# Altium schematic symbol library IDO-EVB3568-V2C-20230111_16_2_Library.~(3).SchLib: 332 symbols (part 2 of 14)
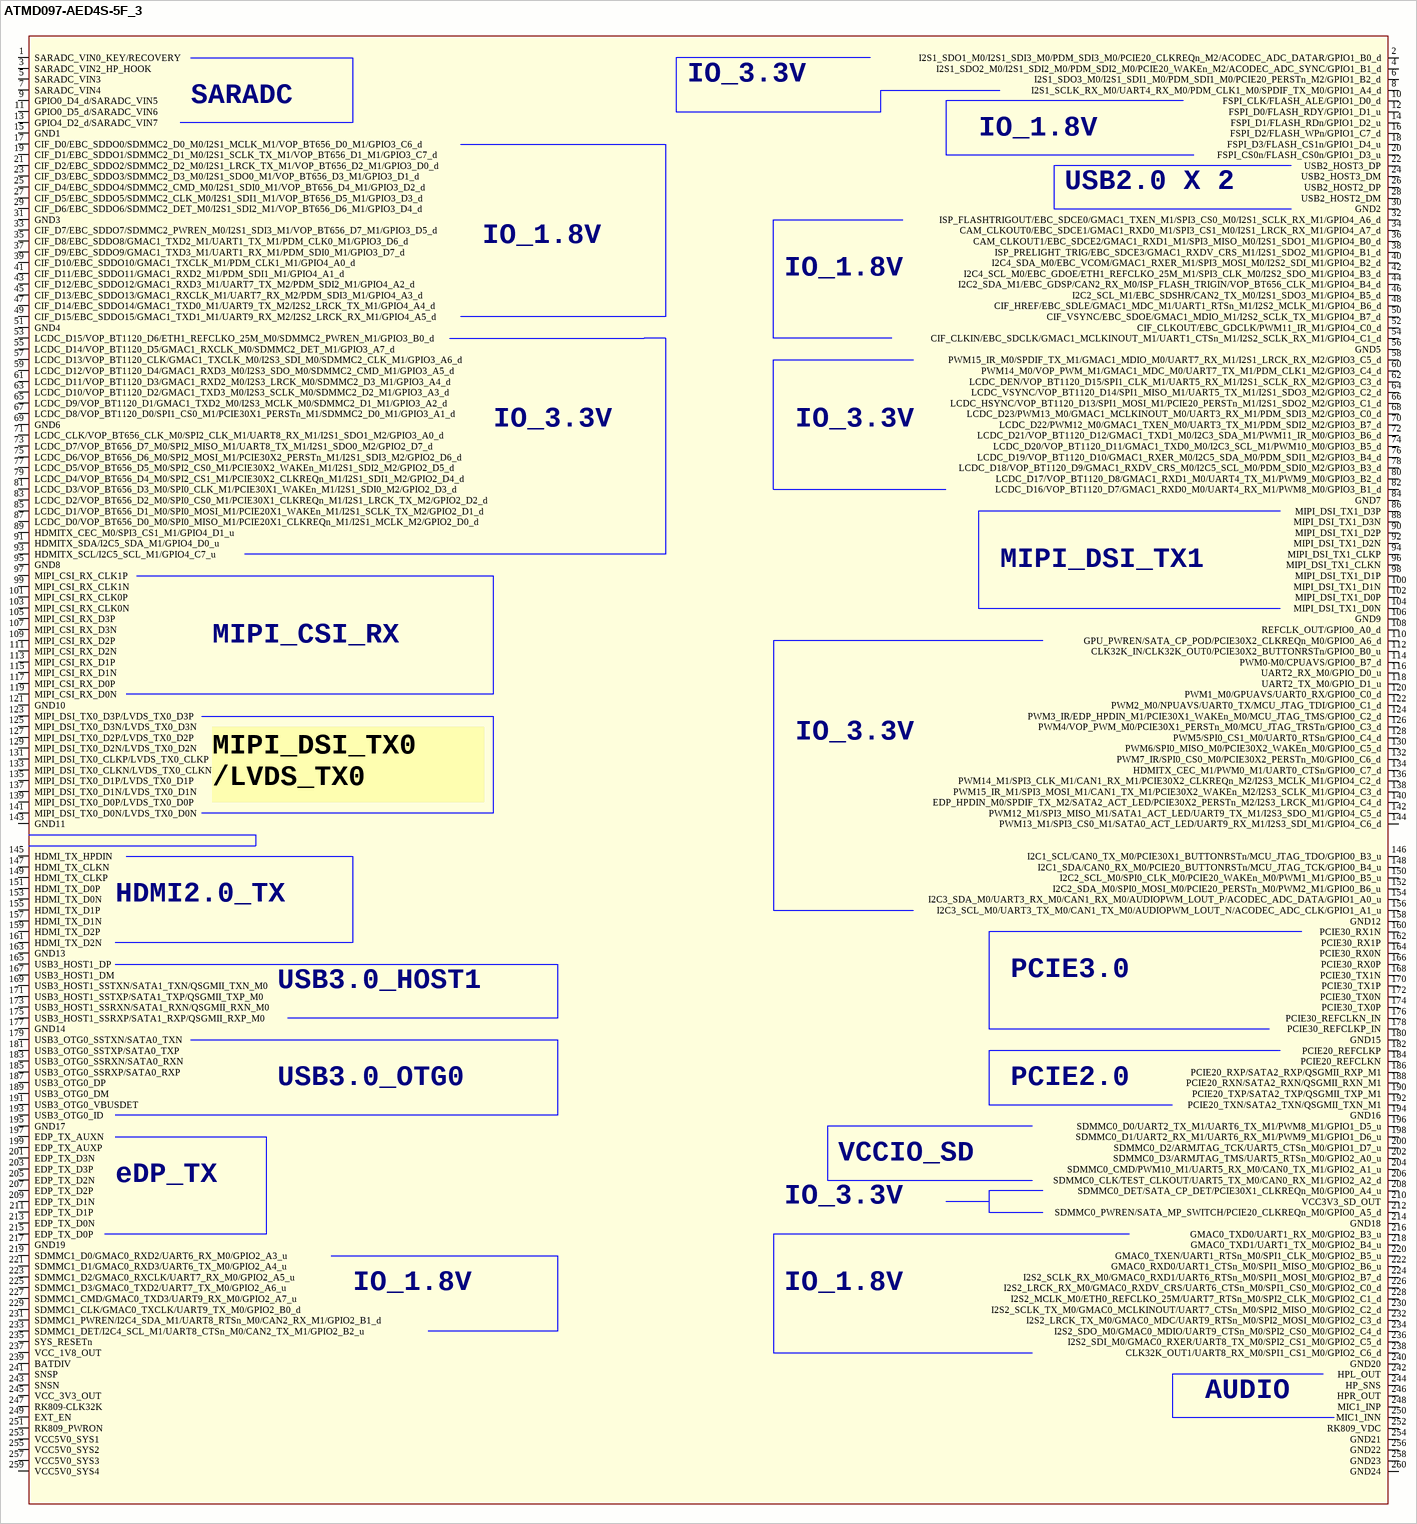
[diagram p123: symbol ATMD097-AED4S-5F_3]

## ATMD097-AED4S-5F_3
designator J?
Altium-Right: 1260; Altium-Bottom: 1360
pins: 1 SARADC_VIN0_KEY/RECOVERY, 2 I2S1_SDO1_M0/I2S1_SDI3_M0/PDM_SDI3_M0/PCIE20_CLKREQn_M2/ACODEC_ADC_DATAR/GPIO1_B0_d, 3 SARADC_VIN2_HP_HOOK, 4 I2S1_SDO2_M0/I2S1_SDI2_M0/PDM_SDI2_M0/PCIE20_WAKEn_M2/ACODEC_ADC_SYNC/GPIO1_B1_d, 5 SARADC_VIN3, 6 I2S1_SDO3_M0/I2S1_SDI1_M0/PDM_SDI1_M0/PCIE20_PERSTn_M2/GPIO1_B2_d, 7 SARADC_VIN4, 8 I2S1_SCLK_RX_M0/UART4_RX_M0/PDM_CLK1_M0/SPDIF_TX_M0/GPIO1_A4_d, 9 GPIO0_D4_d/SARADC_VIN5, 10 FSPI_CLK/FLASH_ALE/GPIO1_D0_d, 11 GPIO0_D5_d/SARADC_VIN6, 12 FSPI_D0/FLASH_RDY/GPIO1_D1_u, 13 GPIO4_D2_d/SARADC_VIN7, 14 FSPI_D1/FLASH_RDn/GPIO1_D2_u, 15 GND1, 16 FSPI_D2/FLASH_WPn/GPIO1_C7_d, 17 CIF_D0/EBC_SDDO0/SDMMC2_D0_M0/I2S1_MCLK_M1/VOP_BT656_D0_M1/GPIO3_C6_d, 18 FSPI_D3/FLASH_CS1n/GPIO1_D4_u, 19 CIF_D1/EBC_SDDO1/SDMMC2_D1_M0/I2S1_SCLK_TX_M1/VOP_BT656_D1_M1/GPIO3_C7_d, 20 FSPI_CS0n/FLASH_CS0n/GPIO1_D3_u, 21 CIF_D2/EBC_SDDO2/SDMMC2_D2_M0/I2S1_LRCK_TX_M1/VOP_BT656_D2_M1/GPIO3_D0_d, 22 USB2_HOST3_DP, 23 CIF_D3/EBC_SDDO3/SDMMC2_D3_M0/I2S1_SDO0_M1/VOP_BT656_D3_M1/GPIO3_D1_d, 24 USB2_HOST3_DM, 25 CIF_D4/EBC_SDDO4/SDMMC2_CMD_M0/I2S1_SDI0_M1/VOP_BT656_D4_M1/GPIO3_D2_d, 26 USB2_HOST2_DP, 27 CIF_D5/EBC_SDDO5/SDMMC2_CLK_M0/I2S1_SDI1_M1/VOP_BT656_D5_M1/GPIO3_D3_d, 28 USB2_HOST2_DM, 29 CIF_D6/EBC_SDDO6/SDMMC2_DET_M0/I2S1_SDI2_M1/VOP_BT656_D6_M1/GPIO3_D4_d, 30 GND2, 31 GND3, 32 ISP_FLASHTRIGOUT/EBC_SDCE0/GMAC1_TXEN_M1/SPI3_CS0_M0/I2S1_SCLK_RX_M1/GPIO4_A6_d, 33 CIF_D7/EBC_SDDO7/SDMMC2_PWREN_M0/I2S1_SDI3_M1/VOP_BT656_D7_M1/GPIO3_D5_d, 34 CAM_CLKOUT0/EBC_SDCE1/GMAC1_RXD0_M1/SPI3_CS1_M0/I2S1_LRCK_RX_M1/GPIO4_A7_d, 35 CIF_D8/EBC_SDDO8/GMAC1_TXD2_M1/UART1_TX_M1/PDM_CLK0_M1/GPIO3_D6_d, 36 CAM_CLKOUT1/EBC_SDCE2/GMAC1_RXD1_M1/SPI3_MISO_M0/I2S1_SDO1_M1/GPIO4_B0_d, 37 CIF_D9/EBC_SDDO9/GMAC1_TXD3_M1/UART1_RX_M1/PDM_SDI0_M1/GPIO3_D7_d, 38 ISP_PRELIGHT_TRIG/EBC_SDCE3/GMAC1_RXDV_CRS_M1/I2S1_SDO2_M1/GPIO4_B1_d, 39 CIF_D10/EBC_SDDO10/GMAC1_TXCLK_M1/PDM_CLK1_M1/GPIO4_A0_d, 40 I2C4_SDA_M0/EBC_VCOM/GMAC1_RXER_M1/SPI3_MOSI_M0/I2S2_SDI_M1/GPIO4_B2_d, 41 CIF_D11/EBC_SDDO11/GMAC1_RXD2_M1/PDM_SDI1_M1/GPIO4_A1_d, 42 I2C4_SCL_M0/EBC_GDOE/ETH1_REFCLKO_25M_M1/SPI3_CLK_M0/I2S2_SDO_M1/GPIO4_B3_d, 43 CIF_D12/EBC_SDDO12/GMAC1_RXD3_M1/UART7_TX_M2/PDM_SDI2_M1/GPIO4_A2_d, 44 I2C2_SDA_M1/EBC_GDSP/CAN2_RX_M0/ISP_FLASH_TRIGIN/VOP_BT656_CLK_M1/GPIO4_B4_d, 45 CIF_D13/EBC_SDDO13/GMAC1_RXCLK_M1/UART7_RX_M2/PDM_SDI3_M1/GPIO4_A3_d, 46 I2C2_SCL_M1/EBC_SDSHR/CAN2_TX_M0/I2S1_SDO3_M1/GPIO4_B5_d, 47 CIF_D14/EBC_SDDO14/GMAC1_TXD0_M1/UART9_TX_M2/I2S2_LRCK_TX_M1/GPIO4_A4_d, 48 CIF_HREF/EBC_SDLE/GMAC1_MDC_M1/UART1_RTSn_M1/I2S2_MCLK_M1/GPIO4_B6_d, 49 CIF_D15/EBC_SDDO15/GMAC1_TXD1_M1/UART9_RX_M2/I2S2_LRCK_RX_M1/GPIO4_A5_d, 50 CIF_VSYNC/EBC_SDOE/GMAC1_MDIO_M1/I2S2_SCLK_TX_M1/GPIO4_B7_d, 51 GND4, 52 CIF_CLKOUT/EBC_GDCLK/PWM11_IR_M1/GPIO4_C0_d, 53 LCDC_D15/VOP_BT1120_D6/ETH1_REFCLKO_25M_M0/SDMMC2_PWREN_M1/GPIO3_B0_d, 54 CIF_CLKIN/EBC_SDCLK/GMAC1_MCLKINOUT_M1/UART1_CTSn_M1/I2S2_SCLK_RX_M1/GPIO4_C1_d, 55 LCDC_D14/VOP_BT1120_D5/GMAC1_RXCLK_M0/SDMMC2_DET_M1/GPIO3_A7_d, 56 GND5, 57 LCDC_D13/VOP_BT1120_CLK/GMAC1_TXCLK_M0/I2S3_SDI_M0/SDMMC2_CLK_M1/GPIO3_A6_d, 58 PWM15_IR_M0/SPDIF_TX_M1/GMAC1_MDIO_M0/UART7_RX_M1/I2S1_LRCK_RX_M2/GPIO3_C5_d, 59 LCDC_D12/VOP_BT1120_D4/GMAC1_RXD3_M0/I2S3_SDO_M0/SDMMC2_CMD_M1/GPIO3_A5_d, 60 PWM14_M0/VOP_PWM_M1/GMAC1_MDC_M0/UART7_TX_M1/PDM_CLK1_M2/GPIO3_C4_d, 61 LCDC_D11/VOP_BT1120_D3/GMAC1_RXD2_M0/I2S3_LRCK_M0/SDMMC2_D3_M1/GPIO3_A4_d, 62 LCDC_DEN/VOP_BT1120_D15/SPI1_CLK_M1/UART5_RX_M1/I2S1_SCLK_RX_M2/GPIO3_C3_d, 63 LCDC_D10/VOP_BT1120_D2/GMAC1_TXD3_M0/I2S3_SCLK_M0/SDMMC2_D2_M1/GPIO3_A3_d, 64 LCDC_VSYNC/VOP_BT1120_D14/SPI1_MISO_M1/UART5_TX_M1/I2S1_SDO3_M2/GPIO3_C2_d, 65 LCDC_D9/VOP_BT1120_D1/GMAC1_TXD2_M0/I2S3_MCLK_M0/SDMMC2_D1_M1/GPIO3_A2_d, 66 LCDC_HSYNC/VOP_BT1120_D13/SPI1_MOSI_M1/PCIE20_PERSTn_M1/I2S1_SDO2_M2/GPIO3_C1_d, 67 LCDC_D8/VOP_BT1120_D0/SPI1_CS0_M1/PCIE30X1_PERSTn_M1/SDMMC2_D0_M1/GPIO3_A1_d, 68 LCDC_D23/PWM13_M0/GMAC1_MCLKINOUT_M0/UART3_RX_M1/PDM_SDI3_M2/GPIO3_C0_d, 69 GND6, 70 LCDC_D22/PWM12_M0/GMAC1_TXEN_M0/UART3_TX_M1/PDM_SDI2_M2/GPIO3_B7_d, 71 LCDC_CLK/VOP_BT656_CLK_M0/SPI2_CLK_M1/UART8_RX_M1/I2S1_SDO1_M2/GPIO3_A0_d, 72 LCDC_D21/VOP_BT1120_D12/GMAC1_TXD1_M0/I2C3_SDA_M1/PWM11_IR_M0/GPIO3_B6_d, 73 LCDC_D7/VOP_BT656_D7_M0/SPI2_MISO_M1/UART8_TX_M1/I2S1_SDO0_M2/GPIO2_D7_d, 74 LCDC_D20/VOP_BT1120_D11/GMAC1_TXD0_M0/I2C3_SCL_M1/PWM10_M0/GPIO3_B5_d, 75 LCDC_D6/VOP_BT656_D6_M0/SPI2_MOSI_M1/PCIE30X2_PERSTn_M1/I2S1_SDI3_M2/GPIO2_D6_d, 76 LCDC_D19/VOP_BT1120_D10/GMAC1_RXER_M0/I2C5_SDA_M0/PDM_SDI1_M2/GPIO3_B4_d, 77 LCDC_D5/VOP_BT656_D5_M0/SPI2_CS0_M1/PCIE30X2_WAKEn_M1/I2S1_SDI2_M2/GPIO2_D5_d, 78 LCDC_D18/VOP_BT1120_D9/GMAC1_RXDV_CRS_M0/I2C5_SCL_M0/PDM_SDI0_M2/GPIO3_B3_d, 79 LCDC_D4/VOP_BT656_D4_M0/SPI2_CS1_M1/PCIE30X2_CLKREQn_M1/I2S1_SDI1_M2/GPIO2_D4_d, 80 LCDC_D17/VOP_BT1120_D8/GMAC1_RXD1_M0/UART4_TX_M1/PWM9_M0/GPIO3_B2_d, 81 LCDC_D3/VOP_BT656_D3_M0/SPI0_CLK_M1/PCIE30X1_WAKEn_M1/I2S1_SDI0_M2/GPIO2_D3_d, 82 LCDC_D16/VOP_BT1120_D7/GMAC1_RXD0_M0/UART4_RX_M1/PWM8_M0/GPIO3_B1_d, 83 LCDC_D2/VOP_BT656_D2_M0/SPI0_CS0_M1/PCIE30X1_CLKREQn_M1/I2S1_LRCK_TX_M2/GPIO2_D2_d, 84 GND7, 85 LCDC_D1/VOP_BT656_D1_M0/SPI0_MOSI_M1/PCIE20X1_WAKEn_M1/I2S1_SCLK_TX_M2/GPIO2_D1_d, 86 MIPI_DSI_TX1_D3P, 87 LCDC_D0/VOP_BT656_D0_M0/SPI0_MISO_M1/PCIE20X1_CLKREQn_M1/I2S1_MCLK_M2/GPIO2_D0_d, 88 MIPI_DSI_TX1_D3N, 89 HDMITX_CEC_M0/SPI3_CS1_M1/GPIO4_D1_u, 90 MIPI_DSI_TX1_D2P, 91 HDMITX_SDA/I2C5_SDA_M1/GPIO4_D0_u, 92 MIPI_DSI_TX1_D2N, 93 HDMITX_SCL/I2C5_SCL_M1/GPIO4_C7_u, 94 MIPI_DSI_TX1_CLKP, 95 GND8, 96 MIPI_DSI_TX1_CLKN, 97 MIPI_CSI_RX_CLK1P, 98 MIPI_DSI_TX1_D1P, 99 MIPI_CSI_RX_CLK1N, 100 MIPI_DSI_TX1_D1N, 101 MIPI_CSI_RX_CLK0P, 102 MIPI_DSI_TX1_D0P, 103 MIPI_CSI_RX_CLK0N, 104 MIPI_DSI_TX1_D0N, 105 MIPI_CSI_RX_D3P, 106 GND9, 107 MIPI_CSI_RX_D3N, 108 REFCLK_OUT/GPIO0_A0_d, 109 MIPI_CSI_RX_D2P, 110 GPU_PWREN/SATA_CP_POD/PCIE30X2_CLKREQn_M0/GPIO0_A6_d, 111 MIPI_CSI_RX_D2N, 112 CLK32K_IN/CLK32K_OUT0/PCIE30X2_BUTTONRSTn/GPIO0_B0_u, 113 MIPI_CSI_RX_D1P, 114 PWM0-M0/CPUAVS/GPIO0_B7_d, 115 MIPI_CSI_RX_D1N, 116 UART2_RX_M0/GPIO_D0_u, 117 MIPI_CSI_RX_D0P, 118 UART2_TX_M0/GPIO_D1_u, 119 MIPI_CSI_RX_D0N, 120 PWM1_M0/GPUAVS/UART0_RX/GPIO0_C0_d, 121 GND10, 122 PWM2_M0/NPUAVS/UART0_TX/MCU_JTAG_TDI/GPIO0_C1_d, 123 MIPI_DSI_TX0_D3P/LVDS_TX0_D3P, 124 PWM3_IR/EDP_HPDIN_M1/PCIE30X1_WAKEn_M0/MCU_JTAG_TMS/GPIO0_C2_d, 125 MIPI_DSI_TX0_D3N/LVDS_TX0_D3N, 126 PWM4/VOP_PWM_M0/PCIE30X1_PERSTn_M0/MCU_JTAG_TRSTn/GPIO0_C3_d, 127 MIPI_DSI_TX0_D2P/LVDS_TX0_D2P, 128 PWM5/SPI0_CS1_M0/UART0_RTSn/GPIO0_C4_d, 129 MIPI_DSI_TX0_D2N/LVDS_TX0_D2N, 130 PWM6/SPI0_MISO_M0/PCIE30X2_WAKEn_M0/GPIO0_C5_d, 131 MIPI_DSI_TX0_CLKP/LVDS_TX0_CLKP, 132 PWM7_IR/SPI0_CS0_M0/PCIE30X2_PERSTn_M0/GPIO0_C6_d, 133 MIPI_DSI_TX0_CLKN/LVDS_TX0_CLKN, 134 HDMITX_CEC_M1/PWM0_M1/UART0_CTSn/GPIO0_C7_d, 135 MIPI_DSI_TX0_D1P/LVDS_TX0_D1P, 136 PWM14_M1/SPI3_CLK_M1/CAN1_RX_M1/PCIE30X2_CLKREQn_M2/I2S3_MCLK_M1/GPIO4_C2_d, 137 MIPI_DSI_TX0_D1N/LVDS_TX0_D1N, 138 PWM15_IR_M1/SPI3_MOSI_M1/CAN1_TX_M1/PCIE30X2_WAKEn_M2/I2S3_SCLK_M1/GPIO4_C3_d, 139 MIPI_DSI_TX0_D0P/LVDS_TX0_D0P, 140 EDP_HPDIN_M0/SPDIF_TX_M2/SATA2_ACT_LED/PCIE30X2_PERSTn_M2/I2S3_LRCK_M1/GPIO4_C4_d, 141 MIPI_DSI_TX0_D0N/LVDS_TX0_D0N, 142 PWM12_M1/SPI3_MISO_M1/SATA1_ACT_LED/UART9_TX_M1/I2S3_SDO_M1/GPIO4_C5_d, 143 GND11, 144 PWM13_M1/SPI3_CS0_M1/SATA0_ACT_LED/UART9_RX_M1/I2S3_SDI_M1/GPIO4_C6_d, 145 HDMI_TX_HPDIN, 146 I2C1_SCL/CAN0_TX_M0/PCIE30X1_BUTTONRSTn/MCU_JTAG_TDO/GPIO0_B3_u, 147 HDMI_TX_CLKN, 148 I2C1_SDA/CAN0_RX_M0/PCIE20_BUTTONRSTn/MCU_JTAG_TCK/GPIO0_B4_u, 149 HDMI_TX_CLKP, 150 I2C2_SCL_M0/SPI0_CLK_M0/PCIE20_WAKEn_M0/PWM1_M1/GPIO0_B5_u, 151 HDMI_TX_D0P, 152 I2C2_SDA_M0/SPI0_MOSI_M0/PCIE20_PERSTn_M0/PWM2_M1/GPIO0_B6_u, 153 HDMI_TX_D0N, 154 I2C3_SDA_M0/UART3_RX_M0/CAN1_RX_M0/AUDIOPWM_LOUT_P/ACODEC_ADC_DATA/GPIO1_A0_u, 155 HDMI_TX_D1P, 156 I2C3_SCL_M0/UART3_TX_M0/CAN1_TX_M0/AUDIOPWM_LOUT_N/ACODEC_ADC_CLK/GPIO1_A1_u, 157 HDMI_TX_D1N, 158 GND12, 159 HDMI_TX_D2P, 160 PCIE30_RX1N, 161 HDMI_TX_D2N, 162 PCIE30_RX1P, 163 GND13, 164 PCIE30_RX0N, 165 USB3_HOST1_DP, 166 PCIE30_RX0P, 167 USB3_HOST1_DM, 168 PCIE30_TX1N, 169 USB3_HOST1_SSTXN/SATA1_TXN/QSGMII_TXN_M0, 170 PCIE30_TX1P, 171 USB3_HOST1_SSTXP/SATA1_TXP/QSGMII_TXP_M0, 172 PCIE30_TX0N, 173 USB3_HOST1_SSRXN/SATA1_RXN/QSGMII_RXN_M0, 174 PCIE30_TX0P, 175 USB3_HOST1_SSRXP/SATA1_RXP/QSGMII_RXP_M0, 176 PCIE30_REFCLKN_IN, 177 GND14, 178 PCIE30_REFCLKP_IN, 179 USB3_OTG0_SSTXN/SATA0_TXN, 180 GND15, 181 USB3_OTG0_SSTXP/SATA0_TXP, 182 PCIE20_REFCLKP, 183 USB3_OTG0_SSRXN/SATA0_RXN, 184 PCIE20_REFCLKN, 185 USB3_OTG0_SSRXP/SATA0_RXP, 186 PCIE20_RXP/SATA2_RXP/QSGMII_RXP_M1, 187 USB3_OTG0_DP, 188 PCIE20_RXN/SATA2_RXN/QSGMII_RXN_M1, 189 USB3_OTG0_DM, 190 PCIE20_TXP/SATA2_TXP/QSGMII_TXP_M1, 191 USB3_OTG0_VBUSDET, 192 PCIE20_TXN/SATA2_TXN/QSGMII_TXN_M1, 193 USB3_OTG0_ID, 194 GND16, 195 GND17, 196 SDMMC0_D0/UART2_TX_M1/UART6_TX_M1/PWM8_M1/GPIO1_D5_u, 197 EDP_TX_AUXN, 198 SDMMC0_D1/UART2_RX_M1/UART6_RX_M1/PWM9_M1/GPIO1_D6_u, 199 EDP_TX_AUXP, 200 SDMMC0_D2/ARMJTAG_TCK/UART5_CTSn_M0/GPIO1_D7_u, 201 EDP_TX_D3N, 202 SDMMC0_D3/ARMJTAG_TMS/UART5_RTSn_M0/GPIO2_A0_u, 203 EDP_TX_D3P, 204 SDMMC0_CMD/PWM10_M1/UART5_RX_M0/CAN0_TX_M1/GPIO2_A1_u, 205 EDP_TX_D2N, 206 SDMMC0_CLK/TEST_CLKOUT/UART5_TX_M0/CAN0_RX_M1/GPIO2_A2_d, 207 EDP_TX_D2P, 208 SDMMC0_DET/SATA_CP_DET/PCIE30X1_CLKREQn_M0/GPIO0_A4_u, 209 EDP_TX_D1N, 210 VCC3V3_SD_OUT, 211 EDP_TX_D1P, 212 SDMMC0_PWREN/SATA_MP_SWITCH/PCIE20_CLKREQn_M0/GPIO0_A5_d, 213 EDP_TX_D0N, 214 GND18, 215 EDP_TX_D0P, 216 GMAC0_TXD0/UART1_RX_M0/GPIO2_B3_u, 217 GND19, 218 GMAC0_TXD1/UART1_TX_M0/GPIO2_B4_u, 219 SDMMC1_D0/GMAC0_RXD2/UART6_RX_M0/GPIO2_A3_u, 220 GMAC0_TXEN/UART1_RTSn_M0/SPI1_CLK_M0/GPIO2_B5_u, 221 SDMMC1_D1/GMAC0_RXD3/UART6_TX_M0/GPIO2_A4_u, 222 GMAC0_RXD0/UART1_CTSn_M0/SPI1_MISO_M0/GPIO2_B6_u, 223 SDMMC1_D2/GMAC0_RXCLK/UART7_RX_M0/GPIO2_A5_u, 224 I2S2_SCLK_RX_M0/GMAC0_RXD1/UART6_RTSn_M0/SPI1_MOSI_M0/GPIO2_B7_d, 225 SDMMC1_D3/GMAC0_TXD2/UART7_TX_M0/GPIO2_A6_u, 226 I2S2_LRCK_RX_M0/GMAC0_RXDV_CRS/UART6_CTSn_M0/SPI1_CS0_M0/GPIO2_C0_d, 227 SDMMC1_CMD/GMAC0_TXD3/UART9_RX_M0/GPIO2_A7_u, 228 I2S2_MCLK_M0/ETH0_REFCLKO_25M/UART7_RTSn_M0/SPI2_CLK_M0/GPIO2_C1_d, 229 SDMMC1_CLK/GMAC0_TXCLK/UART9_TX_M0/GPIO2_B0_d, 230 I2S2_SCLK_TX_M0/GMAC0_MCLKINOUT/UART7_CTSn_M0/SPI2_MISO_M0/GPIO2_C2_d, 231 SDMMC1_PWREN/I2C4_SDA_M1/UART8_RTSn_M0/CAN2_RX_M1/GPIO2_B1_d, 232 I2S2_LRCK_TX_M0/GMAC0_MDC/UART9_RTSn_M0/SPI2_MOSI_M0/GPIO2_C3_d, 233 SDMMC1_DET/I2C4_SCL_M1/UART8_CTSn_M0/CAN2_TX_M1/GPIO2_B2_u, 234 I2S2_SDO_M0/GMAC0_MDIO/UART9_CTSn_M0/SPI2_CS0_M0/GPIO2_C4_d, 235 SYS_RESETn, 236 I2S2_SDI_M0/GMAC0_RXER/UART8_TX_M0/SPI2_CS1_M0/GPIO2_C5_d, 237 VCC_1V8_OUT, 238 CLK32K_OUT1/UART8_RX_M0/SPI1_CS1_M0/GPIO2_C6_d, 239 BATDIV, 240 GND20, 241 SNSP, 242 HPL_OUT, 243 SNSN, 244 HP_SNS, 245 VCC_3V3_OUT, 246 HPR_OUT, 247 RK809-CLK32K, 248 MIC1_INP, 249 EXT_EN, 250 MIC1_INN, 251 RK809_PWRON, 252 RK809_VDC, 253 VCC5V0_SYS1, 254 GND21, 255 VCC5V0_SYS2, 256 GND22, 257 VCC5V0_SYS3, 258 GND23, 259 VCC5V0_SYS4, 260 GND24

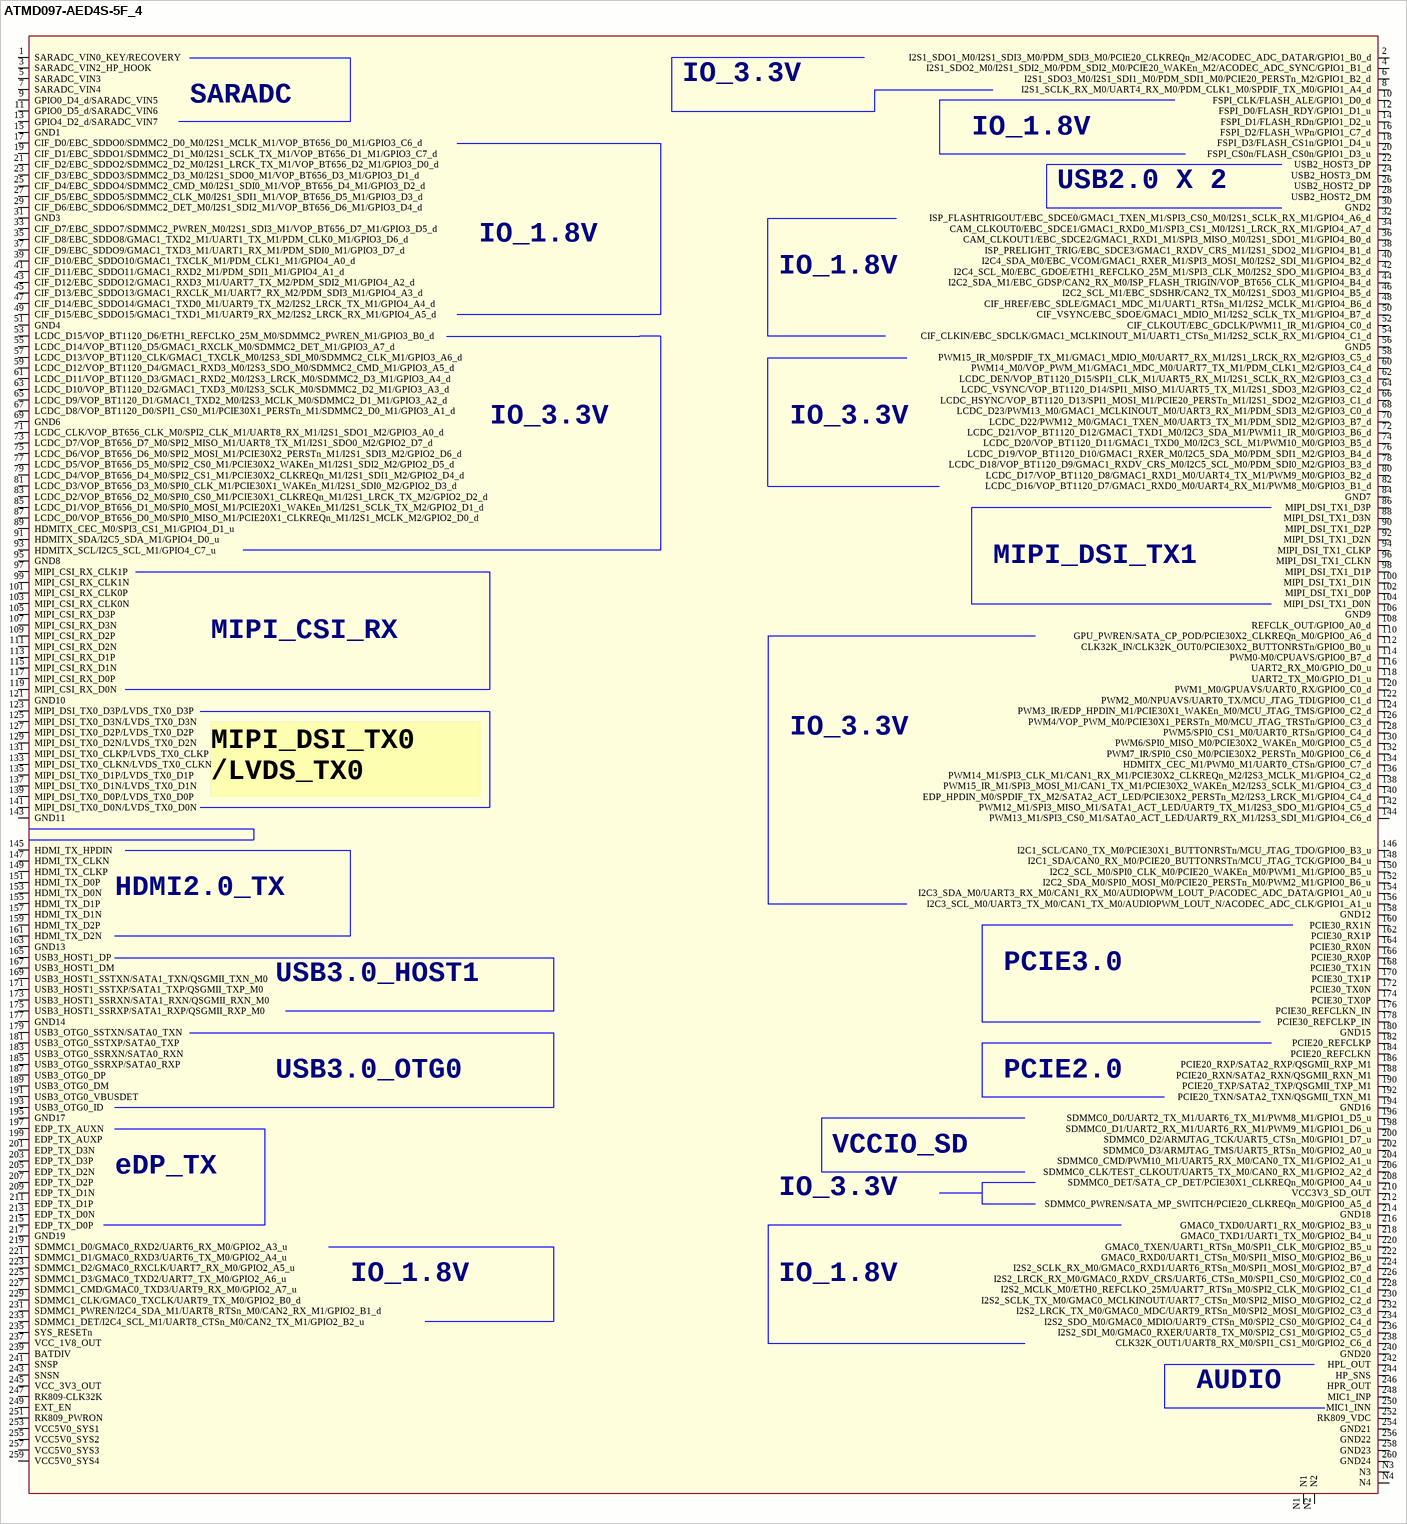
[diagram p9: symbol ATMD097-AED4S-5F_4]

## ATMD097-AED4S-5F_4
designator J?
Altium-Right: 1260; Altium-Bottom: 1360
pins: 1 SARADC_VIN0_KEY/RECOVERY, 2 I2S1_SDO1_M0/I2S1_SDI3_M0/PDM_SDI3_M0/PCIE20_CLKREQn_M2/ACODEC_ADC_DATAR/GPIO1_B0_d, 3 SARADC_VIN2_HP_HOOK, 4 I2S1_SDO2_M0/I2S1_SDI2_M0/PDM_SDI2_M0/PCIE20_WAKEn_M2/ACODEC_ADC_SYNC/GPIO1_B1_d, 5 SARADC_VIN3, 6 I2S1_SDO3_M0/I2S1_SDI1_M0/PDM_SDI1_M0/PCIE20_PERSTn_M2/GPIO1_B2_d, 7 SARADC_VIN4, 8 I2S1_SCLK_RX_M0/UART4_RX_M0/PDM_CLK1_M0/SPDIF_TX_M0/GPIO1_A4_d, 9 GPIO0_D4_d/SARADC_VIN5, 10 FSPI_CLK/FLASH_ALE/GPIO1_D0_d, 11 GPIO0_D5_d/SARADC_VIN6, 12 FSPI_D0/FLASH_RDY/GPIO1_D1_u, 13 GPIO4_D2_d/SARADC_VIN7, 14 FSPI_D1/FLASH_RDn/GPIO1_D2_u, 15 GND1, 16 FSPI_D2/FLASH_WPn/GPIO1_C7_d, 17 CIF_D0/EBC_SDDO0/SDMMC2_D0_M0/I2S1_MCLK_M1/VOP_BT656_D0_M1/GPIO3_C6_d, 18 FSPI_D3/FLASH_CS1n/GPIO1_D4_u, 19 CIF_D1/EBC_SDDO1/SDMMC2_D1_M0/I2S1_SCLK_TX_M1/VOP_BT656_D1_M1/GPIO3_C7_d, 20 FSPI_CS0n/FLASH_CS0n/GPIO1_D3_u, 21 CIF_D2/EBC_SDDO2/SDMMC2_D2_M0/I2S1_LRCK_TX_M1/VOP_BT656_D2_M1/GPIO3_D0_d, 22 USB2_HOST3_DP, 23 CIF_D3/EBC_SDDO3/SDMMC2_D3_M0/I2S1_SDO0_M1/VOP_BT656_D3_M1/GPIO3_D1_d, 24 USB2_HOST3_DM, 25 CIF_D4/EBC_SDDO4/SDMMC2_CMD_M0/I2S1_SDI0_M1/VOP_BT656_D4_M1/GPIO3_D2_d, 26 USB2_HOST2_DP, 27 CIF_D5/EBC_SDDO5/SDMMC2_CLK_M0/I2S1_SDI1_M1/VOP_BT656_D5_M1/GPIO3_D3_d, 28 USB2_HOST2_DM, 29 CIF_D6/EBC_SDDO6/SDMMC2_DET_M0/I2S1_SDI2_M1/VOP_BT656_D6_M1/GPIO3_D4_d, 30 GND2, 31 GND3, 32 ISP_FLASHTRIGOUT/EBC_SDCE0/GMAC1_TXEN_M1/SPI3_CS0_M0/I2S1_SCLK_RX_M1/GPIO4_A6_d, 33 CIF_D7/EBC_SDDO7/SDMMC2_PWREN_M0/I2S1_SDI3_M1/VOP_BT656_D7_M1/GPIO3_D5_d, 34 CAM_CLKOUT0/EBC_SDCE1/GMAC1_RXD0_M1/SPI3_CS1_M0/I2S1_LRCK_RX_M1/GPIO4_A7_d, 35 CIF_D8/EBC_SDDO8/GMAC1_TXD2_M1/UART1_TX_M1/PDM_CLK0_M1/GPIO3_D6_d, 36 CAM_CLKOUT1/EBC_SDCE2/GMAC1_RXD1_M1/SPI3_MISO_M0/I2S1_SDO1_M1/GPIO4_B0_d, 37 CIF_D9/EBC_SDDO9/GMAC1_TXD3_M1/UART1_RX_M1/PDM_SDI0_M1/GPIO3_D7_d, 38 ISP_PRELIGHT_TRIG/EBC_SDCE3/GMAC1_RXDV_CRS_M1/I2S1_SDO2_M1/GPIO4_B1_d, 39 CIF_D10/EBC_SDDO10/GMAC1_TXCLK_M1/PDM_CLK1_M1/GPIO4_A0_d, 40 I2C4_SDA_M0/EBC_VCOM/GMAC1_RXER_M1/SPI3_MOSI_M0/I2S2_SDI_M1/GPIO4_B2_d, 41 CIF_D11/EBC_SDDO11/GMAC1_RXD2_M1/PDM_SDI1_M1/GPIO4_A1_d, 42 I2C4_SCL_M0/EBC_GDOE/ETH1_REFCLKO_25M_M1/SPI3_CLK_M0/I2S2_SDO_M1/GPIO4_B3_d, 43 CIF_D12/EBC_SDDO12/GMAC1_RXD3_M1/UART7_TX_M2/PDM_SDI2_M1/GPIO4_A2_d, 44 I2C2_SDA_M1/EBC_GDSP/CAN2_RX_M0/ISP_FLASH_TRIGIN/VOP_BT656_CLK_M1/GPIO4_B4_d, 45 CIF_D13/EBC_SDDO13/GMAC1_RXCLK_M1/UART7_RX_M2/PDM_SDI3_M1/GPIO4_A3_d, 46 I2C2_SCL_M1/EBC_SDSHR/CAN2_TX_M0/I2S1_SDO3_M1/GPIO4_B5_d, 47 CIF_D14/EBC_SDDO14/GMAC1_TXD0_M1/UART9_TX_M2/I2S2_LRCK_TX_M1/GPIO4_A4_d, 48 CIF_HREF/EBC_SDLE/GMAC1_MDC_M1/UART1_RTSn_M1/I2S2_MCLK_M1/GPIO4_B6_d, 49 CIF_D15/EBC_SDDO15/GMAC1_TXD1_M1/UART9_RX_M2/I2S2_LRCK_RX_M1/GPIO4_A5_d, 50 CIF_VSYNC/EBC_SDOE/GMAC1_MDIO_M1/I2S2_SCLK_TX_M1/GPIO4_B7_d, 51 GND4, 52 CIF_CLKOUT/EBC_GDCLK/PWM11_IR_M1/GPIO4_C0_d, 53 LCDC_D15/VOP_BT1120_D6/ETH1_REFCLKO_25M_M0/SDMMC2_PWREN_M1/GPIO3_B0_d, 54 CIF_CLKIN/EBC_SDCLK/GMAC1_MCLKINOUT_M1/UART1_CTSn_M1/I2S2_SCLK_RX_M1/GPIO4_C1_d, 55 LCDC_D14/VOP_BT1120_D5/GMAC1_RXCLK_M0/SDMMC2_DET_M1/GPIO3_A7_d, 56 GND5, 57 LCDC_D13/VOP_BT1120_CLK/GMAC1_TXCLK_M0/I2S3_SDI_M0/SDMMC2_CLK_M1/GPIO3_A6_d, 58 PWM15_IR_M0/SPDIF_TX_M1/GMAC1_MDIO_M0/UART7_RX_M1/I2S1_LRCK_RX_M2/GPIO3_C5_d, 59 LCDC_D12/VOP_BT1120_D4/GMAC1_RXD3_M0/I2S3_SDO_M0/SDMMC2_CMD_M1/GPIO3_A5_d, 60 PWM14_M0/VOP_PWM_M1/GMAC1_MDC_M0/UART7_TX_M1/PDM_CLK1_M2/GPIO3_C4_d, 61 LCDC_D11/VOP_BT1120_D3/GMAC1_RXD2_M0/I2S3_LRCK_M0/SDMMC2_D3_M1/GPIO3_A4_d, 62 LCDC_DEN/VOP_BT1120_D15/SPI1_CLK_M1/UART5_RX_M1/I2S1_SCLK_RX_M2/GPIO3_C3_d, 63 LCDC_D10/VOP_BT1120_D2/GMAC1_TXD3_M0/I2S3_SCLK_M0/SDMMC2_D2_M1/GPIO3_A3_d, 64 LCDC_VSYNC/VOP_BT1120_D14/SPI1_MISO_M1/UART5_TX_M1/I2S1_SDO3_M2/GPIO3_C2_d, 65 LCDC_D9/VOP_BT1120_D1/GMAC1_TXD2_M0/I2S3_MCLK_M0/SDMMC2_D1_M1/GPIO3_A2_d, 66 LCDC_HSYNC/VOP_BT1120_D13/SPI1_MOSI_M1/PCIE20_PERSTn_M1/I2S1_SDO2_M2/GPIO3_C1_d, 67 LCDC_D8/VOP_BT1120_D0/SPI1_CS0_M1/PCIE30X1_PERSTn_M1/SDMMC2_D0_M1/GPIO3_A1_d, 68 LCDC_D23/PWM13_M0/GMAC1_MCLKINOUT_M0/UART3_RX_M1/PDM_SDI3_M2/GPIO3_C0_d, 69 GND6, 70 LCDC_D22/PWM12_M0/GMAC1_TXEN_M0/UART3_TX_M1/PDM_SDI2_M2/GPIO3_B7_d, 71 LCDC_CLK/VOP_BT656_CLK_M0/SPI2_CLK_M1/UART8_RX_M1/I2S1_SDO1_M2/GPIO3_A0_d, 72 LCDC_D21/VOP_BT1120_D12/GMAC1_TXD1_M0/I2C3_SDA_M1/PWM11_IR_M0/GPIO3_B6_d, 73 LCDC_D7/VOP_BT656_D7_M0/SPI2_MISO_M1/UART8_TX_M1/I2S1_SDO0_M2/GPIO2_D7_d, 74 LCDC_D20/VOP_BT1120_D11/GMAC1_TXD0_M0/I2C3_SCL_M1/PWM10_M0/GPIO3_B5_d, 75 LCDC_D6/VOP_BT656_D6_M0/SPI2_MOSI_M1/PCIE30X2_PERSTn_M1/I2S1_SDI3_M2/GPIO2_D6_d, 76 LCDC_D19/VOP_BT1120_D10/GMAC1_RXER_M0/I2C5_SDA_M0/PDM_SDI1_M2/GPIO3_B4_d, 77 LCDC_D5/VOP_BT656_D5_M0/SPI2_CS0_M1/PCIE30X2_WAKEn_M1/I2S1_SDI2_M2/GPIO2_D5_d, 78 LCDC_D18/VOP_BT1120_D9/GMAC1_RXDV_CRS_M0/I2C5_SCL_M0/PDM_SDI0_M2/GPIO3_B3_d, 79 LCDC_D4/VOP_BT656_D4_M0/SPI2_CS1_M1/PCIE30X2_CLKREQn_M1/I2S1_SDI1_M2/GPIO2_D4_d, 80 LCDC_D17/VOP_BT1120_D8/GMAC1_RXD1_M0/UART4_TX_M1/PWM9_M0/GPIO3_B2_d, 81 LCDC_D3/VOP_BT656_D3_M0/SPI0_CLK_M1/PCIE30X1_WAKEn_M1/I2S1_SDI0_M2/GPIO2_D3_d, 82 LCDC_D16/VOP_BT1120_D7/GMAC1_RXD0_M0/UART4_RX_M1/PWM8_M0/GPIO3_B1_d, 83 LCDC_D2/VOP_BT656_D2_M0/SPI0_CS0_M1/PCIE30X1_CLKREQn_M1/I2S1_LRCK_TX_M2/GPIO2_D2_d, 84 GND7, 85 LCDC_D1/VOP_BT656_D1_M0/SPI0_MOSI_M1/PCIE20X1_WAKEn_M1/I2S1_SCLK_TX_M2/GPIO2_D1_d, 86 MIPI_DSI_TX1_D3P, 87 LCDC_D0/VOP_BT656_D0_M0/SPI0_MISO_M1/PCIE20X1_CLKREQn_M1/I2S1_MCLK_M2/GPIO2_D0_d, 88 MIPI_DSI_TX1_D3N, 89 HDMITX_CEC_M0/SPI3_CS1_M1/GPIO4_D1_u, 90 MIPI_DSI_TX1_D2P, 91 HDMITX_SDA/I2C5_SDA_M1/GPIO4_D0_u, 92 MIPI_DSI_TX1_D2N, 93 HDMITX_SCL/I2C5_SCL_M1/GPIO4_C7_u, 94 MIPI_DSI_TX1_CLKP, 95 GND8, 96 MIPI_DSI_TX1_CLKN, 97 MIPI_CSI_RX_CLK1P, 98 MIPI_DSI_TX1_D1P, 99 MIPI_CSI_RX_CLK1N, 100 MIPI_DSI_TX1_D1N, 101 MIPI_CSI_RX_CLK0P, 102 MIPI_DSI_TX1_D0P, 103 MIPI_CSI_RX_CLK0N, 104 MIPI_DSI_TX1_D0N, 105 MIPI_CSI_RX_D3P, 106 GND9, 107 MIPI_CSI_RX_D3N, 108 REFCLK_OUT/GPIO0_A0_d, 109 MIPI_CSI_RX_D2P, 110 GPU_PWREN/SATA_CP_POD/PCIE30X2_CLKREQn_M0/GPIO0_A6_d, 111 MIPI_CSI_RX_D2N, 112 CLK32K_IN/CLK32K_OUT0/PCIE30X2_BUTTONRSTn/GPIO0_B0_u, 113 MIPI_CSI_RX_D1P, 114 PWM0-M0/CPUAVS/GPIO0_B7_d, 115 MIPI_CSI_RX_D1N, 116 UART2_RX_M0/GPIO_D0_u, 117 MIPI_CSI_RX_D0P, 118 UART2_TX_M0/GPIO_D1_u, 119 MIPI_CSI_RX_D0N, 120 PWM1_M0/GPUAVS/UART0_RX/GPIO0_C0_d, 121 GND10, 122 PWM2_M0/NPUAVS/UART0_TX/MCU_JTAG_TDI/GPIO0_C1_d, 123 MIPI_DSI_TX0_D3P/LVDS_TX0_D3P, 124 PWM3_IR/EDP_HPDIN_M1/PCIE30X1_WAKEn_M0/MCU_JTAG_TMS/GPIO0_C2_d, 125 MIPI_DSI_TX0_D3N/LVDS_TX0_D3N, 126 PWM4/VOP_PWM_M0/PCIE30X1_PERSTn_M0/MCU_JTAG_TRSTn/GPIO0_C3_d, 127 MIPI_DSI_TX0_D2P/LVDS_TX0_D2P, 128 PWM5/SPI0_CS1_M0/UART0_RTSn/GPIO0_C4_d, 129 MIPI_DSI_TX0_D2N/LVDS_TX0_D2N, 130 PWM6/SPI0_MISO_M0/PCIE30X2_WAKEn_M0/GPIO0_C5_d, 131 MIPI_DSI_TX0_CLKP/LVDS_TX0_CLKP, 132 PWM7_IR/SPI0_CS0_M0/PCIE30X2_PERSTn_M0/GPIO0_C6_d, 133 MIPI_DSI_TX0_CLKN/LVDS_TX0_CLKN, 134 HDMITX_CEC_M1/PWM0_M1/UART0_CTSn/GPIO0_C7_d, 135 MIPI_DSI_TX0_D1P/LVDS_TX0_D1P, 136 PWM14_M1/SPI3_CLK_M1/CAN1_RX_M1/PCIE30X2_CLKREQn_M2/I2S3_MCLK_M1/GPIO4_C2_d, 137 MIPI_DSI_TX0_D1N/LVDS_TX0_D1N, 138 PWM15_IR_M1/SPI3_MOSI_M1/CAN1_TX_M1/PCIE30X2_WAKEn_M2/I2S3_SCLK_M1/GPIO4_C3_d, 139 MIPI_DSI_TX0_D0P/LVDS_TX0_D0P, 140 EDP_HPDIN_M0/SPDIF_TX_M2/SATA2_ACT_LED/PCIE30X2_PERSTn_M2/I2S3_LRCK_M1/GPIO4_C4_d, 141 MIPI_DSI_TX0_D0N/LVDS_TX0_D0N, 142 PWM12_M1/SPI3_MISO_M1/SATA1_ACT_LED/UART9_TX_M1/I2S3_SDO_M1/GPIO4_C5_d, 143 GND11, 144 PWM13_M1/SPI3_CS0_M1/SATA0_ACT_LED/UART9_RX_M1/I2S3_SDI_M1/GPIO4_C6_d, 145 HDMI_TX_HPDIN, 146 I2C1_SCL/CAN0_TX_M0/PCIE30X1_BUTTONRSTn/MCU_JTAG_TDO/GPIO0_B3_u, 147 HDMI_TX_CLKN, 148 I2C1_SDA/CAN0_RX_M0/PCIE20_BUTTONRSTn/MCU_JTAG_TCK/GPIO0_B4_u, 149 HDMI_TX_CLKP, 150 I2C2_SCL_M0/SPI0_CLK_M0/PCIE20_WAKEn_M0/PWM1_M1/GPIO0_B5_u, 151 HDMI_TX_D0P, 152 I2C2_SDA_M0/SPI0_MOSI_M0/PCIE20_PERSTn_M0/PWM2_M1/GPIO0_B6_u, 153 HDMI_TX_D0N, 154 I2C3_SDA_M0/UART3_RX_M0/CAN1_RX_M0/AUDIOPWM_LOUT_P/ACODEC_ADC_DATA/GPIO1_A0_u, 155 HDMI_TX_D1P, 156 I2C3_SCL_M0/UART3_TX_M0/CAN1_TX_M0/AUDIOPWM_LOUT_N/ACODEC_ADC_CLK/GPIO1_A1_u, 157 HDMI_TX_D1N, 158 GND12, 159 HDMI_TX_D2P, 160 PCIE30_RX1N, 161 HDMI_TX_D2N, 162 PCIE30_RX1P, 163 GND13, 164 PCIE30_RX0N, 165 USB3_HOST1_DP, 166 PCIE30_RX0P, 167 USB3_HOST1_DM, 168 PCIE30_TX1N, 169 USB3_HOST1_SSTXN/SATA1_TXN/QSGMII_TXN_M0, 170 PCIE30_TX1P, 171 USB3_HOST1_SSTXP/SATA1_TXP/QSGMII_TXP_M0, 172 PCIE30_TX0N, 173 USB3_HOST1_SSRXN/SATA1_RXN/QSGMII_RXN_M0, 174 PCIE30_TX0P, 175 USB3_HOST1_SSRXP/SATA1_RXP/QSGMII_RXP_M0, 176 PCIE30_REFCLKN_IN, 177 GND14, 178 PCIE30_REFCLKP_IN, 179 USB3_OTG0_SSTXN/SATA0_TXN, 180 GND15, 181 USB3_OTG0_SSTXP/SATA0_TXP, 182 PCIE20_REFCLKP, 183 USB3_OTG0_SSRXN/SATA0_RXN, 184 PCIE20_REFCLKN, 185 USB3_OTG0_SSRXP/SATA0_RXP, 186 PCIE20_RXP/SATA2_RXP/QSGMII_RXP_M1, 187 USB3_OTG0_DP, 188 PCIE20_RXN/SATA2_RXN/QSGMII_RXN_M1, 189 USB3_OTG0_DM, 190 PCIE20_TXP/SATA2_TXP/QSGMII_TXP_M1, 191 USB3_OTG0_VBUSDET, 192 PCIE20_TXN/SATA2_TXN/QSGMII_TXN_M1, 193 USB3_OTG0_ID, 194 GND16, 195 GND17, 196 SDMMC0_D0/UART2_TX_M1/UART6_TX_M1/PWM8_M1/GPIO1_D5_u, 197 EDP_TX_AUXN, 198 SDMMC0_D1/UART2_RX_M1/UART6_RX_M1/PWM9_M1/GPIO1_D6_u, 199 EDP_TX_AUXP, 200 SDMMC0_D2/ARMJTAG_TCK/UART5_CTSn_M0/GPIO1_D7_u, 201 EDP_TX_D3N, 202 SDMMC0_D3/ARMJTAG_TMS/UART5_RTSn_M0/GPIO2_A0_u, 203 EDP_TX_D3P, 204 SDMMC0_CMD/PWM10_M1/UART5_RX_M0/CAN0_TX_M1/GPIO2_A1_u, 205 EDP_TX_D2N, 206 SDMMC0_CLK/TEST_CLKOUT/UART5_TX_M0/CAN0_RX_M1/GPIO2_A2_d, 207 EDP_TX_D2P, 208 SDMMC0_DET/SATA_CP_DET/PCIE30X1_CLKREQn_M0/GPIO0_A4_u, 209 EDP_TX_D1N, 210 VCC3V3_SD_OUT, 211 EDP_TX_D1P, 212 SDMMC0_PWREN/SATA_MP_SWITCH/PCIE20_CLKREQn_M0/GPIO0_A5_d, 213 EDP_TX_D0N, 214 GND18, 215 EDP_TX_D0P, 216 GMAC0_TXD0/UART1_RX_M0/GPIO2_B3_u, 217 GND19, 218 GMAC0_TXD1/UART1_TX_M0/GPIO2_B4_u, 219 SDMMC1_D0/GMAC0_RXD2/UART6_RX_M0/GPIO2_A3_u, 220 GMAC0_TXEN/UART1_RTSn_M0/SPI1_CLK_M0/GPIO2_B5_u, 221 SDMMC1_D1/GMAC0_RXD3/UART6_TX_M0/GPIO2_A4_u, 222 GMAC0_RXD0/UART1_CTSn_M0/SPI1_MISO_M0/GPIO2_B6_u, 223 SDMMC1_D2/GMAC0_RXCLK/UART7_RX_M0/GPIO2_A5_u, 224 I2S2_SCLK_RX_M0/GMAC0_RXD1/UART6_RTSn_M0/SPI1_MOSI_M0/GPIO2_B7_d, 225 SDMMC1_D3/GMAC0_TXD2/UART7_TX_M0/GPIO2_A6_u, 226 I2S2_LRCK_RX_M0/GMAC0_RXDV_CRS/UART6_CTSn_M0/SPI1_CS0_M0/GPIO2_C0_d, 227 SDMMC1_CMD/GMAC0_TXD3/UART9_RX_M0/GPIO2_A7_u, 228 I2S2_MCLK_M0/ETH0_REFCLKO_25M/UART7_RTSn_M0/SPI2_CLK_M0/GPIO2_C1_d, 229 SDMMC1_CLK/GMAC0_TXCLK/UART9_TX_M0/GPIO2_B0_d, 230 I2S2_SCLK_TX_M0/GMAC0_MCLKINOUT/UART7_CTSn_M0/SPI2_MISO_M0/GPIO2_C2_d, 231 SDMMC1_PWREN/I2C4_SDA_M1/UART8_RTSn_M0/CAN2_RX_M1/GPIO2_B1_d, 232 I2S2_LRCK_TX_M0/GMAC0_MDC/UART9_RTSn_M0/SPI2_MOSI_M0/GPIO2_C3_d, 233 SDMMC1_DET/I2C4_SCL_M1/UART8_CTSn_M0/CAN2_TX_M1/GPIO2_B2_u, 234 I2S2_SDO_M0/GMAC0_MDIO/UART9_CTSn_M0/SPI2_CS0_M0/GPIO2_C4_d, 235 SYS_RESETn, 236 I2S2_SDI_M0/GMAC0_RXER/UART8_TX_M0/SPI2_CS1_M0/GPIO2_C5_d, 237 VCC_1V8_OUT, 238 CLK32K_OUT1/UART8_RX_M0/SPI1_CS1_M0/GPIO2_C6_d, 239 BATDIV, 240 GND20, 241 SNSP, 242 HPL_OUT, 243 SNSN, 244 HP_SNS, 245 VCC_3V3_OUT, 246 HPR_OUT, 247 RK809-CLK32K, 248 MIC1_INP, 249 EXT_EN, 250 MIC1_INN, 251 RK809_PWRON, 252 RK809_VDC, 253 VCC5V0_SYS1, 254 GND21, 255 VCC5V0_SYS2, 256 GND22, 257 VCC5V0_SYS3, 258 GND23, 259 VCC5V0_SYS4, 260 GND24, N1, N2, N3, N4

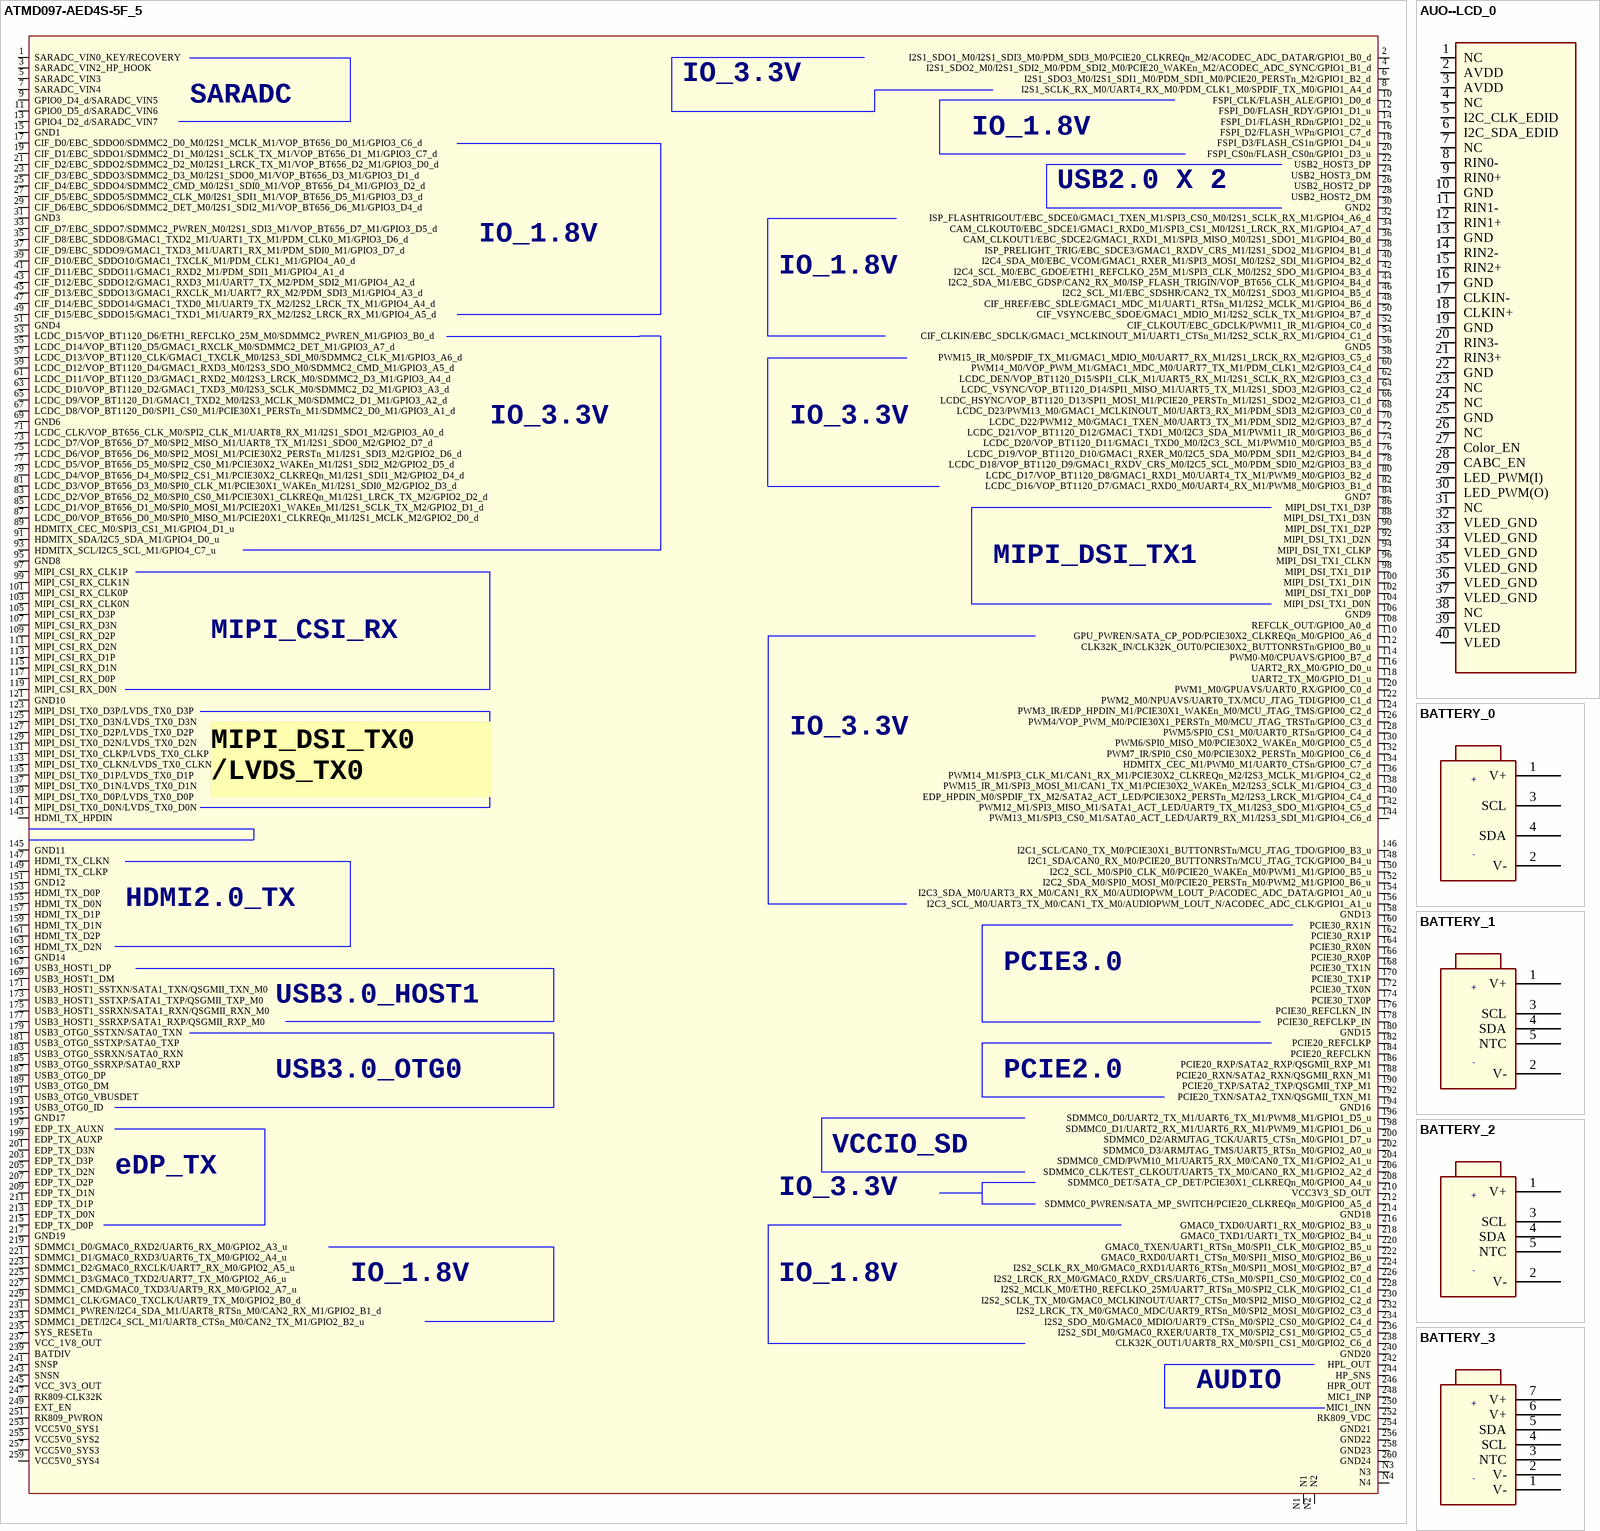
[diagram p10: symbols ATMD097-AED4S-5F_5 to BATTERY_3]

## ATMD097-AED4S-5F_5
designator J?
Altium-Right: 1260; Altium-Bottom: 1360
pins: 1 SARADC_VIN0_KEY/RECOVERY, 2 I2S1_SDO1_M0/I2S1_SDI3_M0/PDM_SDI3_M0/PCIE20_CLKREQn_M2/ACODEC_ADC_DATAR/GPIO1_B0_d, 3 SARADC_VIN2_HP_HOOK, 4 I2S1_SDO2_M0/I2S1_SDI2_M0/PDM_SDI2_M0/PCIE20_WAKEn_M2/ACODEC_ADC_SYNC/GPIO1_B1_d, 5 SARADC_VIN3, 6 I2S1_SDO3_M0/I2S1_SDI1_M0/PDM_SDI1_M0/PCIE20_PERSTn_M2/GPIO1_B2_d, 7 SARADC_VIN4, 8 I2S1_SCLK_RX_M0/UART4_RX_M0/PDM_CLK1_M0/SPDIF_TX_M0/GPIO1_A4_d, 9 GPIO0_D4_d/SARADC_VIN5, 10 FSPI_CLK/FLASH_ALE/GPIO1_D0_d, 11 GPIO0_D5_d/SARADC_VIN6, 12 FSPI_D0/FLASH_RDY/GPIO1_D1_u, 13 GPIO4_D2_d/SARADC_VIN7, 14 FSPI_D1/FLASH_RDn/GPIO1_D2_u, 15 GND1, 16 FSPI_D2/FLASH_WPn/GPIO1_C7_d, 17 CIF_D0/EBC_SDDO0/SDMMC2_D0_M0/I2S1_MCLK_M1/VOP_BT656_D0_M1/GPIO3_C6_d, 18 FSPI_D3/FLASH_CS1n/GPIO1_D4_u, 19 CIF_D1/EBC_SDDO1/SDMMC2_D1_M0/I2S1_SCLK_TX_M1/VOP_BT656_D1_M1/GPIO3_C7_d, 20 FSPI_CS0n/FLASH_CS0n/GPIO1_D3_u, 21 CIF_D2/EBC_SDDO2/SDMMC2_D2_M0/I2S1_LRCK_TX_M1/VOP_BT656_D2_M1/GPIO3_D0_d, 22 USB2_HOST3_DP, 23 CIF_D3/EBC_SDDO3/SDMMC2_D3_M0/I2S1_SDO0_M1/VOP_BT656_D3_M1/GPIO3_D1_d, 24 USB2_HOST3_DM, 25 CIF_D4/EBC_SDDO4/SDMMC2_CMD_M0/I2S1_SDI0_M1/VOP_BT656_D4_M1/GPIO3_D2_d, 26 USB2_HOST2_DP, 27 CIF_D5/EBC_SDDO5/SDMMC2_CLK_M0/I2S1_SDI1_M1/VOP_BT656_D5_M1/GPIO3_D3_d, 28 USB2_HOST2_DM, 29 CIF_D6/EBC_SDDO6/SDMMC2_DET_M0/I2S1_SDI2_M1/VOP_BT656_D6_M1/GPIO3_D4_d, 30 GND2, 31 GND3, 32 ISP_FLASHTRIGOUT/EBC_SDCE0/GMAC1_TXEN_M1/SPI3_CS0_M0/I2S1_SCLK_RX_M1/GPIO4_A6_d, 33 CIF_D7/EBC_SDDO7/SDMMC2_PWREN_M0/I2S1_SDI3_M1/VOP_BT656_D7_M1/GPIO3_D5_d, 34 CAM_CLKOUT0/EBC_SDCE1/GMAC1_RXD0_M1/SPI3_CS1_M0/I2S1_LRCK_RX_M1/GPIO4_A7_d, 35 CIF_D8/EBC_SDDO8/GMAC1_TXD2_M1/UART1_TX_M1/PDM_CLK0_M1/GPIO3_D6_d, 36 CAM_CLKOUT1/EBC_SDCE2/GMAC1_RXD1_M1/SPI3_MISO_M0/I2S1_SDO1_M1/GPIO4_B0_d, 37 CIF_D9/EBC_SDDO9/GMAC1_TXD3_M1/UART1_RX_M1/PDM_SDI0_M1/GPIO3_D7_d, 38 ISP_PRELIGHT_TRIG/EBC_SDCE3/GMAC1_RXDV_CRS_M1/I2S1_SDO2_M1/GPIO4_B1_d, 39 CIF_D10/EBC_SDDO10/GMAC1_TXCLK_M1/PDM_CLK1_M1/GPIO4_A0_d, 40 I2C4_SDA_M0/EBC_VCOM/GMAC1_RXER_M1/SPI3_MOSI_M0/I2S2_SDI_M1/GPIO4_B2_d, 41 CIF_D11/EBC_SDDO11/GMAC1_RXD2_M1/PDM_SDI1_M1/GPIO4_A1_d, 42 I2C4_SCL_M0/EBC_GDOE/ETH1_REFCLKO_25M_M1/SPI3_CLK_M0/I2S2_SDO_M1/GPIO4_B3_d, 43 CIF_D12/EBC_SDDO12/GMAC1_RXD3_M1/UART7_TX_M2/PDM_SDI2_M1/GPIO4_A2_d, 44 I2C2_SDA_M1/EBC_GDSP/CAN2_RX_M0/ISP_FLASH_TRIGIN/VOP_BT656_CLK_M1/GPIO4_B4_d, 45 CIF_D13/EBC_SDDO13/GMAC1_RXCLK_M1/UART7_RX_M2/PDM_SDI3_M1/GPIO4_A3_d, 46 I2C2_SCL_M1/EBC_SDSHR/CAN2_TX_M0/I2S1_SDO3_M1/GPIO4_B5_d, 47 CIF_D14/EBC_SDDO14/GMAC1_TXD0_M1/UART9_TX_M2/I2S2_LRCK_TX_M1/GPIO4_A4_d, 48 CIF_HREF/EBC_SDLE/GMAC1_MDC_M1/UART1_RTSn_M1/I2S2_MCLK_M1/GPIO4_B6_d, 49 CIF_D15/EBC_SDDO15/GMAC1_TXD1_M1/UART9_RX_M2/I2S2_LRCK_RX_M1/GPIO4_A5_d, 50 CIF_VSYNC/EBC_SDOE/GMAC1_MDIO_M1/I2S2_SCLK_TX_M1/GPIO4_B7_d, 51 GND4, 52 CIF_CLKOUT/EBC_GDCLK/PWM11_IR_M1/GPIO4_C0_d, 53 LCDC_D15/VOP_BT1120_D6/ETH1_REFCLKO_25M_M0/SDMMC2_PWREN_M1/GPIO3_B0_d, 54 CIF_CLKIN/EBC_SDCLK/GMAC1_MCLKINOUT_M1/UART1_CTSn_M1/I2S2_SCLK_RX_M1/GPIO4_C1_d, 55 LCDC_D14/VOP_BT1120_D5/GMAC1_RXCLK_M0/SDMMC2_DET_M1/GPIO3_A7_d, 56 GND5, 57 LCDC_D13/VOP_BT1120_CLK/GMAC1_TXCLK_M0/I2S3_SDI_M0/SDMMC2_CLK_M1/GPIO3_A6_d, 58 PWM15_IR_M0/SPDIF_TX_M1/GMAC1_MDIO_M0/UART7_RX_M1/I2S1_LRCK_RX_M2/GPIO3_C5_d, 59 LCDC_D12/VOP_BT1120_D4/GMAC1_RXD3_M0/I2S3_SDO_M0/SDMMC2_CMD_M1/GPIO3_A5_d, 60 PWM14_M0/VOP_PWM_M1/GMAC1_MDC_M0/UART7_TX_M1/PDM_CLK1_M2/GPIO3_C4_d, 61 LCDC_D11/VOP_BT1120_D3/GMAC1_RXD2_M0/I2S3_LRCK_M0/SDMMC2_D3_M1/GPIO3_A4_d, 62 LCDC_DEN/VOP_BT1120_D15/SPI1_CLK_M1/UART5_RX_M1/I2S1_SCLK_RX_M2/GPIO3_C3_d, 63 LCDC_D10/VOP_BT1120_D2/GMAC1_TXD3_M0/I2S3_SCLK_M0/SDMMC2_D2_M1/GPIO3_A3_d, 64 LCDC_VSYNC/VOP_BT1120_D14/SPI1_MISO_M1/UART5_TX_M1/I2S1_SDO3_M2/GPIO3_C2_d, 65 LCDC_D9/VOP_BT1120_D1/GMAC1_TXD2_M0/I2S3_MCLK_M0/SDMMC2_D1_M1/GPIO3_A2_d, 66 LCDC_HSYNC/VOP_BT1120_D13/SPI1_MOSI_M1/PCIE20_PERSTn_M1/I2S1_SDO2_M2/GPIO3_C1_d, 67 LCDC_D8/VOP_BT1120_D0/SPI1_CS0_M1/PCIE30X1_PERSTn_M1/SDMMC2_D0_M1/GPIO3_A1_d, 68 LCDC_D23/PWM13_M0/GMAC1_MCLKINOUT_M0/UART3_RX_M1/PDM_SDI3_M2/GPIO3_C0_d, 69 GND6, 70 LCDC_D22/PWM12_M0/GMAC1_TXEN_M0/UART3_TX_M1/PDM_SDI2_M2/GPIO3_B7_d, 71 LCDC_CLK/VOP_BT656_CLK_M0/SPI2_CLK_M1/UART8_RX_M1/I2S1_SDO1_M2/GPIO3_A0_d, 72 LCDC_D21/VOP_BT1120_D12/GMAC1_TXD1_M0/I2C3_SDA_M1/PWM11_IR_M0/GPIO3_B6_d, 73 LCDC_D7/VOP_BT656_D7_M0/SPI2_MISO_M1/UART8_TX_M1/I2S1_SDO0_M2/GPIO2_D7_d, 74 LCDC_D20/VOP_BT1120_D11/GMAC1_TXD0_M0/I2C3_SCL_M1/PWM10_M0/GPIO3_B5_d, 75 LCDC_D6/VOP_BT656_D6_M0/SPI2_MOSI_M1/PCIE30X2_PERSTn_M1/I2S1_SDI3_M2/GPIO2_D6_d, 76 LCDC_D19/VOP_BT1120_D10/GMAC1_RXER_M0/I2C5_SDA_M0/PDM_SDI1_M2/GPIO3_B4_d, 77 LCDC_D5/VOP_BT656_D5_M0/SPI2_CS0_M1/PCIE30X2_WAKEn_M1/I2S1_SDI2_M2/GPIO2_D5_d, 78 LCDC_D18/VOP_BT1120_D9/GMAC1_RXDV_CRS_M0/I2C5_SCL_M0/PDM_SDI0_M2/GPIO3_B3_d, 79 LCDC_D4/VOP_BT656_D4_M0/SPI2_CS1_M1/PCIE30X2_CLKREQn_M1/I2S1_SDI1_M2/GPIO2_D4_d, 80 LCDC_D17/VOP_BT1120_D8/GMAC1_RXD1_M0/UART4_TX_M1/PWM9_M0/GPIO3_B2_d, 81 LCDC_D3/VOP_BT656_D3_M0/SPI0_CLK_M1/PCIE30X1_WAKEn_M1/I2S1_SDI0_M2/GPIO2_D3_d, 82 LCDC_D16/VOP_BT1120_D7/GMAC1_RXD0_M0/UART4_RX_M1/PWM8_M0/GPIO3_B1_d, 83 LCDC_D2/VOP_BT656_D2_M0/SPI0_CS0_M1/PCIE30X1_CLKREQn_M1/I2S1_LRCK_TX_M2/GPIO2_D2_d, 84 GND7, 85 LCDC_D1/VOP_BT656_D1_M0/SPI0_MOSI_M1/PCIE20X1_WAKEn_M1/I2S1_SCLK_TX_M2/GPIO2_D1_d, 86 MIPI_DSI_TX1_D3P, 87 LCDC_D0/VOP_BT656_D0_M0/SPI0_MISO_M1/PCIE20X1_CLKREQn_M1/I2S1_MCLK_M2/GPIO2_D0_d, 88 MIPI_DSI_TX1_D3N, 89 HDMITX_CEC_M0/SPI3_CS1_M1/GPIO4_D1_u, 90 MIPI_DSI_TX1_D2P, 91 HDMITX_SDA/I2C5_SDA_M1/GPIO4_D0_u, 92 MIPI_DSI_TX1_D2N, 93 HDMITX_SCL/I2C5_SCL_M1/GPIO4_C7_u, 94 MIPI_DSI_TX1_CLKP, 95 GND8, 96 MIPI_DSI_TX1_CLKN, 97 MIPI_CSI_RX_CLK1P, 98 MIPI_DSI_TX1_D1P, 99 MIPI_CSI_RX_CLK1N, 100 MIPI_DSI_TX1_D1N, 101 MIPI_CSI_RX_CLK0P, 102 MIPI_DSI_TX1_D0P, 103 MIPI_CSI_RX_CLK0N, 104 MIPI_DSI_TX1_D0N, 105 MIPI_CSI_RX_D3P, 106 GND9, 107 MIPI_CSI_RX_D3N, 108 REFCLK_OUT/GPIO0_A0_d, 109 MIPI_CSI_RX_D2P, 110 GPU_PWREN/SATA_CP_POD/PCIE30X2_CLKREQn_M0/GPIO0_A6_d, 111 MIPI_CSI_RX_D2N, 112 CLK32K_IN/CLK32K_OUT0/PCIE30X2_BUTTONRSTn/GPIO0_B0_u, 113 MIPI_CSI_RX_D1P, 114 PWM0-M0/CPUAVS/GPIO0_B7_d, 115 MIPI_CSI_RX_D1N, 116 UART2_RX_M0/GPIO_D0_u, 117 MIPI_CSI_RX_D0P, 118 UART2_TX_M0/GPIO_D1_u, 119 MIPI_CSI_RX_D0N, 120 PWM1_M0/GPUAVS/UART0_RX/GPIO0_C0_d, 121 GND10, 122 PWM2_M0/NPUAVS/UART0_TX/MCU_JTAG_TDI/GPIO0_C1_d, 123 MIPI_DSI_TX0_D3P/LVDS_TX0_D3P, 124 PWM3_IR/EDP_HPDIN_M1/PCIE30X1_WAKEn_M0/MCU_JTAG_TMS/GPIO0_C2_d, 125 MIPI_DSI_TX0_D3N/LVDS_TX0_D3N, 126 PWM4/VOP_PWM_M0/PCIE30X1_PERSTn_M0/MCU_JTAG_TRSTn/GPIO0_C3_d, 127 MIPI_DSI_TX0_D2P/LVDS_TX0_D2P, 128 PWM5/SPI0_CS1_M0/UART0_RTSn/GPIO0_C4_d, 129 MIPI_DSI_TX0_D2N/LVDS_TX0_D2N, 130 PWM6/SPI0_MISO_M0/PCIE30X2_WAKEn_M0/GPIO0_C5_d, 131 MIPI_DSI_TX0_CLKP/LVDS_TX0_CLKP, 132 PWM7_IR/SPI0_CS0_M0/PCIE30X2_PERSTn_M0/GPIO0_C6_d, 133 MIPI_DSI_TX0_CLKN/LVDS_TX0_CLKN, 134 HDMITX_CEC_M1/PWM0_M1/UART0_CTSn/GPIO0_C7_d, 135 MIPI_DSI_TX0_D1P/LVDS_TX0_D1P, 136 PWM14_M1/SPI3_CLK_M1/CAN1_RX_M1/PCIE30X2_CLKREQn_M2/I2S3_MCLK_M1/GPIO4_C2_d, 137 MIPI_DSI_TX0_D1N/LVDS_TX0_D1N, 138 PWM15_IR_M1/SPI3_MOSI_M1/CAN1_TX_M1/PCIE30X2_WAKEn_M2/I2S3_SCLK_M1/GPIO4_C3_d, 139 MIPI_DSI_TX0_D0P/LVDS_TX0_D0P, 140 EDP_HPDIN_M0/SPDIF_TX_M2/SATA2_ACT_LED/PCIE30X2_PERSTn_M2/I2S3_LRCK_M1/GPIO4_C4_d, 141 MIPI_DSI_TX0_D0N/LVDS_TX0_D0N, 142 PWM12_M1/SPI3_MISO_M1/SATA1_ACT_LED/UART9_TX_M1/I2S3_SDO_M1/GPIO4_C5_d, 143 HDMI_TX_HPDIN, 144 PWM13_M1/SPI3_CS0_M1/SATA0_ACT_LED/UART9_RX_M1/I2S3_SDI_M1/GPIO4_C6_d, 145 GND11, 146 I2C1_SCL/CAN0_TX_M0/PCIE30X1_BUTTONRSTn/MCU_JTAG_TDO/GPIO0_B3_u, 147 HDMI_TX_CLKN, 148 I2C1_SDA/CAN0_RX_M0/PCIE20_BUTTONRSTn/MCU_JTAG_TCK/GPIO0_B4_u, 149 HDMI_TX_CLKP, 150 I2C2_SCL_M0/SPI0_CLK_M0/PCIE20_WAKEn_M0/PWM1_M1/GPIO0_B5_u, 151 GND12, 152 I2C2_SDA_M0/SPI0_MOSI_M0/PCIE20_PERSTn_M0/PWM2_M1/GPIO0_B6_u, 153 HDMI_TX_D0P, 154 I2C3_SDA_M0/UART3_RX_M0/CAN1_RX_M0/AUDIOPWM_LOUT_P/ACODEC_ADC_DATA/GPIO1_A0_u, 155 HDMI_TX_D0N, 156 I2C3_SCL_M0/UART3_TX_M0/CAN1_TX_M0/AUDIOPWM_LOUT_N/ACODEC_ADC_CLK/GPIO1_A1_u, 157 HDMI_TX_D1P, 158 GND13, 159 HDMI_TX_D1N, 160 PCIE30_RX1N, 161 HDMI_TX_D2P, 162 PCIE30_RX1P, 163 HDMI_TX_D2N, 164 PCIE30_RX0N, 165 GND14, 166 PCIE30_RX0P, 167 USB3_HOST1_DP, 168 PCIE30_TX1N, 169 USB3_HOST1_DM, 170 PCIE30_TX1P, 171 USB3_HOST1_SSTXN/SATA1_TXN/QSGMII_TXN_M0, 172 PCIE30_TX0N, 173 USB3_HOST1_SSTXP/SATA1_TXP/QSGMII_TXP_M0, 174 PCIE30_TX0P, 175 USB3_HOST1_SSRXN/SATA1_RXN/QSGMII_RXN_M0, 176 PCIE30_REFCLKN_IN, 177 USB3_HOST1_SSRXP/SATA1_RXP/QSGMII_RXP_M0, 178 PCIE30_REFCLKP_IN, 179 USB3_OTG0_SSTXN/SATA0_TXN, 180 GND15, 181 USB3_OTG0_SSTXP/SATA0_TXP, 182 PCIE20_REFCLKP, 183 USB3_OTG0_SSRXN/SATA0_RXN, 184 PCIE20_REFCLKN, 185 USB3_OTG0_SSRXP/SATA0_RXP, 186 PCIE20_RXP/SATA2_RXP/QSGMII_RXP_M1, 187 USB3_OTG0_DP, 188 PCIE20_RXN/SATA2_RXN/QSGMII_RXN_M1, 189 USB3_OTG0_DM, 190 PCIE20_TXP/SATA2_TXP/QSGMII_TXP_M1, 191 USB3_OTG0_VBUSDET, 192 PCIE20_TXN/SATA2_TXN/QSGMII_TXN_M1, 193 USB3_OTG0_ID, 194 GND16, 195 GND17, 196 SDMMC0_D0/UART2_TX_M1/UART6_TX_M1/PWM8_M1/GPIO1_D5_u, 197 EDP_TX_AUXN, 198 SDMMC0_D1/UART2_RX_M1/UART6_RX_M1/PWM9_M1/GPIO1_D6_u, 199 EDP_TX_AUXP, 200 SDMMC0_D2/ARMJTAG_TCK/UART5_CTSn_M0/GPIO1_D7_u, 201 EDP_TX_D3N, 202 SDMMC0_D3/ARMJTAG_TMS/UART5_RTSn_M0/GPIO2_A0_u, 203 EDP_TX_D3P, 204 SDMMC0_CMD/PWM10_M1/UART5_RX_M0/CAN0_TX_M1/GPIO2_A1_u, 205 EDP_TX_D2N, 206 SDMMC0_CLK/TEST_CLKOUT/UART5_TX_M0/CAN0_RX_M1/GPIO2_A2_d, 207 EDP_TX_D2P, 208 SDMMC0_DET/SATA_CP_DET/PCIE30X1_CLKREQn_M0/GPIO0_A4_u, 209 EDP_TX_D1N, 210 VCC3V3_SD_OUT, 211 EDP_TX_D1P, 212 SDMMC0_PWREN/SATA_MP_SWITCH/PCIE20_CLKREQn_M0/GPIO0_A5_d, 213 EDP_TX_D0N, 214 GND18, 215 EDP_TX_D0P, 216 GMAC0_TXD0/UART1_RX_M0/GPIO2_B3_u, 217 GND19, 218 GMAC0_TXD1/UART1_TX_M0/GPIO2_B4_u, 219 SDMMC1_D0/GMAC0_RXD2/UART6_RX_M0/GPIO2_A3_u, 220 GMAC0_TXEN/UART1_RTSn_M0/SPI1_CLK_M0/GPIO2_B5_u, 221 SDMMC1_D1/GMAC0_RXD3/UART6_TX_M0/GPIO2_A4_u, 222 GMAC0_RXD0/UART1_CTSn_M0/SPI1_MISO_M0/GPIO2_B6_u, 223 SDMMC1_D2/GMAC0_RXCLK/UART7_RX_M0/GPIO2_A5_u, 224 I2S2_SCLK_RX_M0/GMAC0_RXD1/UART6_RTSn_M0/SPI1_MOSI_M0/GPIO2_B7_d, 225 SDMMC1_D3/GMAC0_TXD2/UART7_TX_M0/GPIO2_A6_u, 226 I2S2_LRCK_RX_M0/GMAC0_RXDV_CRS/UART6_CTSn_M0/SPI1_CS0_M0/GPIO2_C0_d, 227 SDMMC1_CMD/GMAC0_TXD3/UART9_RX_M0/GPIO2_A7_u, 228 I2S2_MCLK_M0/ETH0_REFCLKO_25M/UART7_RTSn_M0/SPI2_CLK_M0/GPIO2_C1_d, 229 SDMMC1_CLK/GMAC0_TXCLK/UART9_TX_M0/GPIO2_B0_d, 230 I2S2_SCLK_TX_M0/GMAC0_MCLKINOUT/UART7_CTSn_M0/SPI2_MISO_M0/GPIO2_C2_d, 231 SDMMC1_PWREN/I2C4_SDA_M1/UART8_RTSn_M0/CAN2_RX_M1/GPIO2_B1_d, 232 I2S2_LRCK_TX_M0/GMAC0_MDC/UART9_RTSn_M0/SPI2_MOSI_M0/GPIO2_C3_d, 233 SDMMC1_DET/I2C4_SCL_M1/UART8_CTSn_M0/CAN2_TX_M1/GPIO2_B2_u, 234 I2S2_SDO_M0/GMAC0_MDIO/UART9_CTSn_M0/SPI2_CS0_M0/GPIO2_C4_d, 235 SYS_RESETn, 236 I2S2_SDI_M0/GMAC0_RXER/UART8_TX_M0/SPI2_CS1_M0/GPIO2_C5_d, 237 VCC_1V8_OUT, 238 CLK32K_OUT1/UART8_RX_M0/SPI1_CS1_M0/GPIO2_C6_d, 239 BATDIV, 240 GND20, 241 SNSP, 242 HPL_OUT, 243 SNSN, 244 HP_SNS, 245 VCC_3V3_OUT, 246 HPR_OUT, 247 RK809-CLK32K, 248 MIC1_INP, 249 EXT_EN, 250 MIC1_INN, 251 RK809_PWRON, 252 RK809_VDC, 253 VCC5V0_SYS1, 254 GND21, 255 VCC5V0_SYS2, 256 GND22, 257 VCC5V0_SYS3, 258 GND23, 259 VCC5V0_SYS4, 260 GND24, N1, N2, N3, N4

## AUO--LCD_0
designator U?
Altium-Right: 80; Altium-Bottom: 420
pins: 1 NC, 2 AVDD, 3 AVDD, 4 NC, 5 I2C_CLK_EDID, 6 I2C_SDA_EDID, 7 NC, 8 RIN0-, 9 RIN0+, 10 GND, 11 RIN1-, 12 RIN1+, 13 GND, 14 RIN2-, 15 RIN2+, 16 GND, 17 CLKIN-, 18 CLKIN+, 19 GND, 20 RIN3-, 21 RIN3+, 22 GND, 23 NC, 24 NC, 25 GND, 26 NC, 27 Color_EN, 28 CABC_EN, 29 LED_PWM(I), 30 LED_PWM(O), 31 NC, 32 VLED_GND, 33 VLED_GND, 34 VLED_GND, 35 VLED_GND, 36 VLED_GND, 37 VLED_GND, 38 NC, 39 VLED, 40 VLED

## BATTERY_0
designator BT?
Altium-Right: 50; Altium-Bottom: 90
pins: 1 V+, 2 V-, 3 SCL, 4 SDA

## BATTERY_1
designator BT?
Altium-Right: 50; Altium-Bottom: 90
pins: 1 V+, 2 V-, 3 SCL, 4 SDA, 5 NTC

## BATTERY_2
designator BT?
Altium-Right: 50; Altium-Bottom: 90
pins: 1 V+, 2 V-, 3 SCL, 4 SDA, 5 NTC

## BATTERY_3
designator BT?
Altium-Right: 50; Altium-Bottom: 90
pins: 1 V-, 2 V-, 3 NTC, 4 SCL, 5 SDA, 6 V+, 7 V+

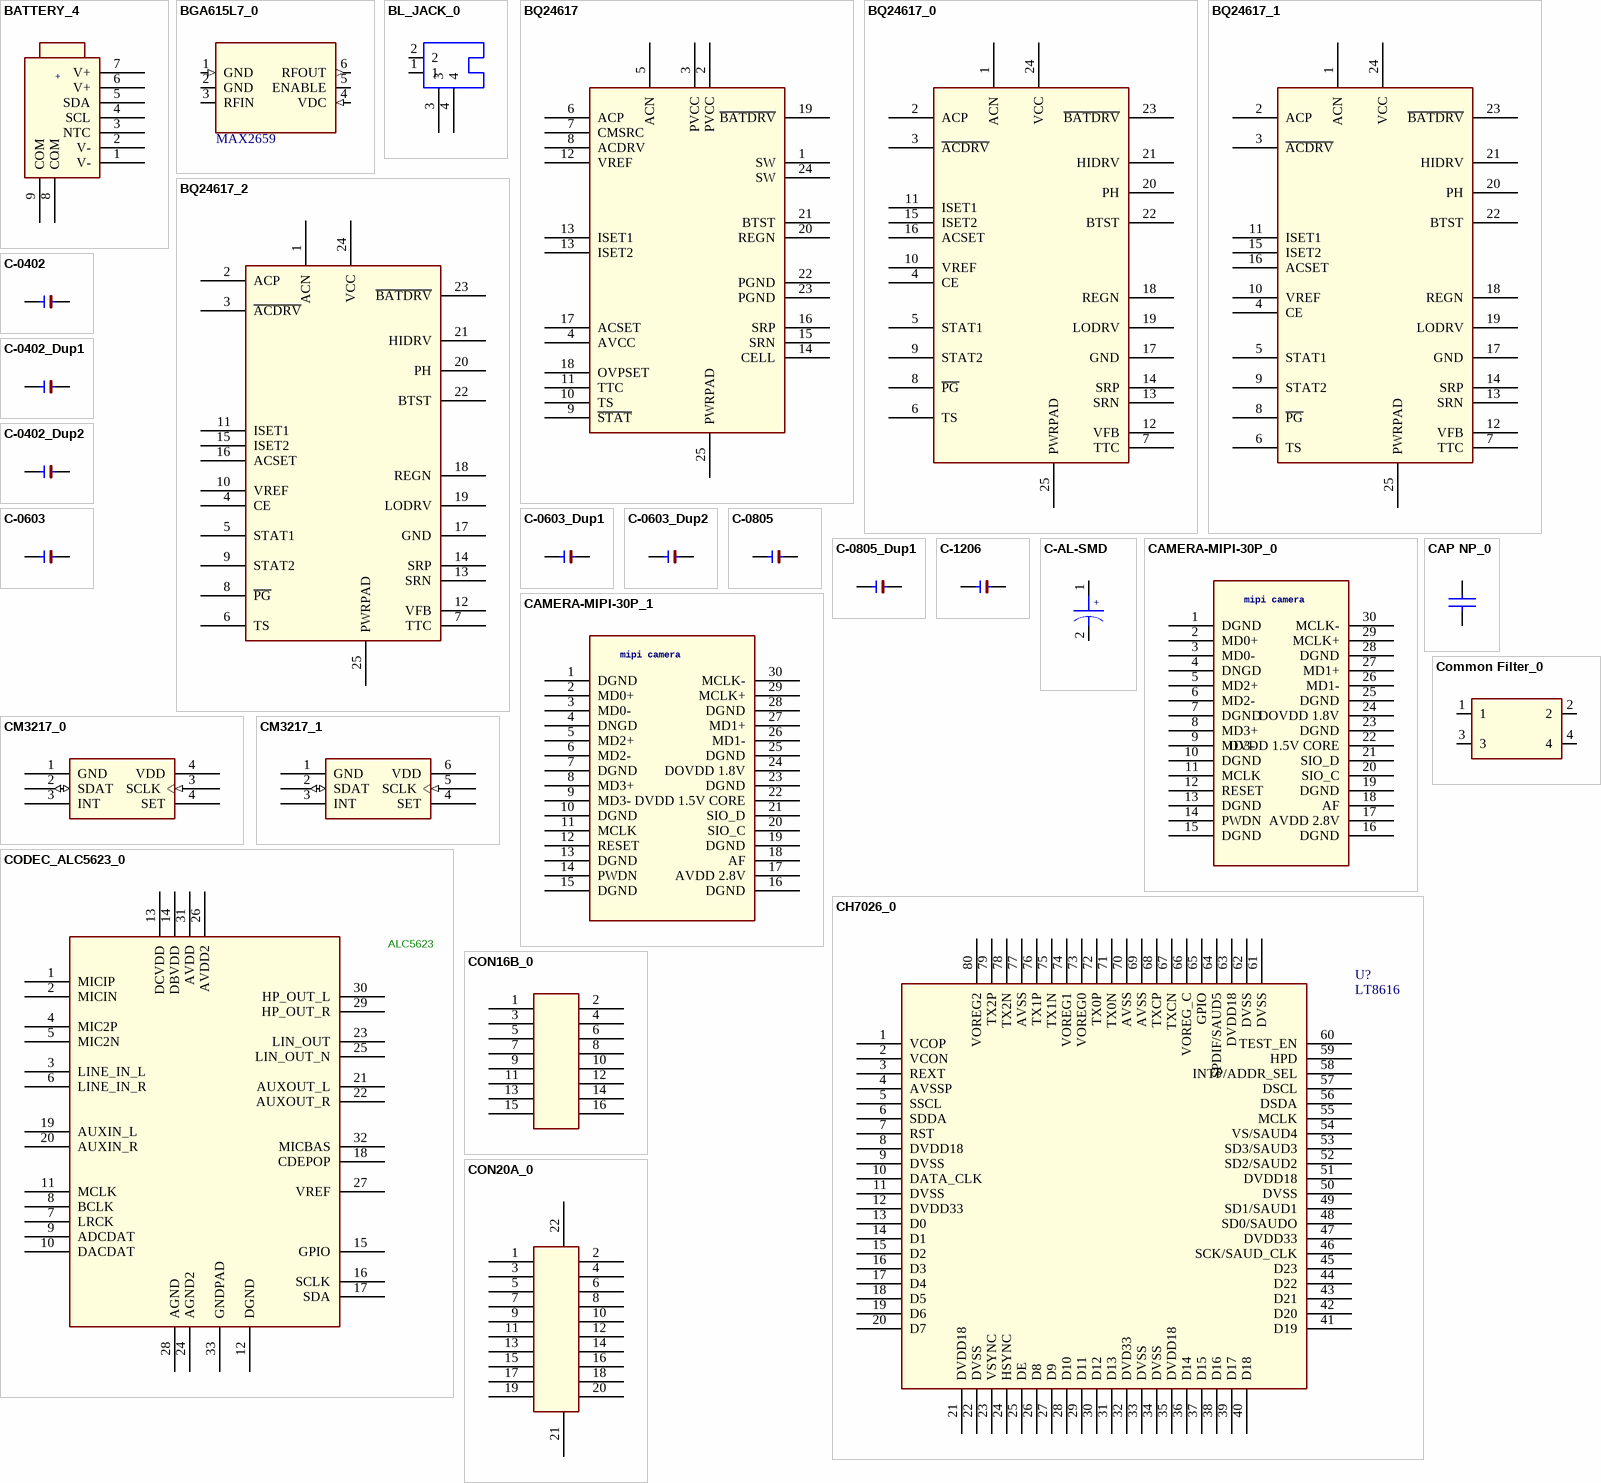
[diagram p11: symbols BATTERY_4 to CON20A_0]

## BATTERY_4
designator BT?
Altium-Right: 50; Altium-Bottom: 90
pins: 1 V- (power), 2 V- (power), 3 NTC, 4 SCL, 5 SDA, 6 V+ (power), 7 V+ (power), 8 COM, 9 COM

## BGA615L7_0
designator U?, comment MAX2659
Altium-Right: 80; Altium-Bottom: 60
footprint P-TSLP-7-1
pins: 1 GND (in), 2 GND, 3 RFIN (power), 4 VDC (in), 5 ENABLE (power), 6 RFOUT (out)

## BL_JACK_0
designator J?
Altium-Right: 40; Altium-Bottom: 30
pins: 1, 2, 3, 4

## BQ24617
designator U?
Altium-Right: 130; Altium-Bottom: 230
footprint QFN24
pins: 1 SW, 2 PVCC, 3 PVCC, 4 AVCC, 5 ACN, 6 ACP, 7 CMSRC, 8 ACDRV, 9 ~{STAT}, 10 TS, 11 TTC, 12 VREF, 13 ISET1, 13 ISET2, 14 CELL, 15 SRN, 16 SRP, 17 ACSET, 18 OVPSET, 19 ~{BATDRV}, 20 REGN, 21 BTST, 22 PGND, 23 PGND, 24 SW, 25 PWRPAD

## BQ24617_0
designator U?
Altium-Right: 130; Altium-Bottom: 250
footprint QFN24
pins: 1 ACN, 2 ACP, 3 ~{ACDRV}, 4 CE, 5 STAT1, 6 TS, 7 TTC, 8 ~{PG}, 9 STAT2, 10 VREF, 11 ISET1, 12 VFB, 13 SRN, 14 SRP, 15 ISET2, 16 ACSET, 17 GND, 18 REGN, 19 LODRV, 20 PH, 21 HIDRV, 22 BTST, 23 ~{BATDRV}, 24 VCC, 25 PWRPAD

## BQ24617_1
designator U?
Altium-Right: 130; Altium-Bottom: 250
footprint QFN24
pins: 1 ACN, 2 ACP, 3 ~{ACDRV}, 4 CE, 5 STAT1, 6 TS, 7 TTC, 8 ~{PG}, 9 STAT2, 10 VREF, 11 ISET1, 12 VFB, 13 SRN, 14 SRP, 15 ISET2, 16 ACSET, 17 GND, 18 REGN, 19 LODRV, 20 PH, 21 HIDRV, 22 BTST, 23 ~{BATDRV}, 24 VCC, 25 PWRPAD

## BQ24617_2
designator U?
Altium-Right: 130; Altium-Bottom: 250
footprint QFN24
pins: 1 ACN, 2 ACP, 3 ~{ACDRV}, 4 CE, 5 STAT1, 6 TS, 7 TTC, 8 ~{PG}, 9 STAT2, 10 VREF, 11 ISET1, 12 VFB, 13 SRN, 14 SRP, 15 ISET2, 16 ACSET, 17 GND, 18 REGN, 19 LODRV, 20 PH, 21 HIDRV, 22 BTST, 23 ~{BATDRV}, 24 VCC, 25 PWRPAD

## C-0402
designator C?
Altium-Right: 10; Altium-Bottom: 20
footprint 1206
pins: 1, 2

## C-0402_Dup1
designator C?
Altium-Right: 10; Altium-Bottom: 20
footprint 1206
pins: 1, 2

## C-0402_Dup2
designator C?
Altium-Right: 10; Altium-Bottom: 20
footprint 1206
pins: 1, 2

## C-0603
designator C?
Altium-Right: 10; Altium-Bottom: 20
footprint 1206
pins: 1, 2

## C-0603_Dup1
designator C?
Altium-Right: 10; Altium-Bottom: 20
footprint 1206
pins: 1, 2

## C-0603_Dup2
designator C?
Altium-Right: 10; Altium-Bottom: 20
footprint 1206
pins: 1, 2

## C-0805
designator C?
Altium-Right: 10; Altium-Bottom: 20
footprint 1206
pins: 1, 2

## C-0805_Dup1
designator C?
Altium-Right: 10; Altium-Bottom: 20
footprint 1206
pins: 1, 2

## C-1206
designator C?
Altium-Right: 10; Altium-Bottom: 20
footprint 1206
pins: 1, 2

## C-AL-SMD
designator CP?
Altium-Right: 20
pins: 1, 2

## CAMERA-MIPI-30P_0
designator U?
Altium-Right: 90; Altium-Bottom: 190
pins: 1 DGND, 2 MD0+, 3 MD0-, 4 DNGD, 5 MD2+, 6 MD2-, 7 DGND, 8 MD3+, 9 MD3-, 10 DGND, 11 MCLK, 12 RESET, 13 DGND, 14 PWDN, 15 DGND, 16 DGND, 17 AVDD 2.8V, 18 AF, 19 DGND, 20 SIO_C, 21 SIO_D, 22 DVDD 1.5V CORE, 23 DGND, 24 DOVDD 1.8V, 25 DGND, 26 MD1-, 27 MD1+, 28 DGND, 29 MCLK+, 30 MCLK-

## CAMERA-MIPI-30P_1
designator U?
Altium-Right: 110; Altium-Bottom: 190
pins: 1 DGND, 2 MD0+, 3 MD0-, 4 DNGD, 5 MD2+, 6 MD2-, 7 DGND, 8 MD3+, 9 MD3-, 10 DGND, 11 MCLK, 12 RESET, 13 DGND, 14 PWDN, 15 DGND, 16 DGND, 17 AVDD 2.8V, 18 AF, 19 DGND, 20 SIO_C, 21 SIO_D, 22 DVDD 1.5V CORE, 23 DGND, 24 DOVDD 1.8V, 25 DGND, 26 MD1-, 27 MD1+, 28 DGND, 29 MCLK+, 30 MCLK-

## CAP NP_0
designator C?
Altium-Right: 20; Altium-Bottom: 10
pins: 1, 2

## CH7026_0
designator U?, comment LT8616
Altium-Right: 270
footprint LQFP80
pins: 1 VCOP, 2 VCON, 3 REXT, 4 AVSSP, 5 SSCL, 6 SDDA, 7 RST, 8 DVDD18 (power), 9 DVSS (power), 10 DATA_CLK, 11 DVSS (power), 12 DVDD33 (power), 13 D0, 14 D1, 15 D2, 16 D3, 17 D4, 18 D5, 19 D6, 20 D7, 21 DVDD18 (power), 22 DVSS (power), 23 VSYNC, 24 HSYNC, 25 DE, 26 D8, 27 D9, 28 D10, 29 D11, 30 D12, 31 D13, 32 DVD33 (power), 33 DVSS (power), 34 DVSS (power), 35 DVDD18 (power), 36 D14, 37 D15, 38 D16, 39 D17, 40 D18, 41 D19, 42 D20, 43 D21, 44 D22, 45 D23, 46 SCK/SAUD_CLK, 47 DVDD33 (power), 48 SD0/SAUDO, 49 SD1/SAUD1, 50 DVSS (power), 51 DVDD18 (power), 52 SD2/SAUD2, 53 SD3/SAUD3, 54 VS/SAUD4, 55 MCLK, 56 DSDA, 57 DSCL, 58 INTP/ADDR_SEL, 59 HPD, 60 TEST_EN, 61 DVSS (power), 62 DVSS (power), 63 DVDD18 (power), 64 SPDIF/SAUD5, 65 GPIO, 66 VOREG_C, 67 TXCN, 68 TXCP, 69 AVSS (power), 70 AVSS (power), 71 TX0N, 72 TX0P, 73 VOREG0, 74 VOREG1, 75 TX1N, 76 TX1P, 77 AVSS (power), 78 TX2N, 79 TX2P, 80 VOREG2

## CM3217_0
designator U?
Altium-Right: 70; Altium-Bottom: 40
footprint CM3217
pins: 1 GND (power), 2 SDAT (io), 3 SCLK (in), 3 INT, 4 SET, 4 VDD (power)

## CM3217_1
designator U?
Altium-Right: 70; Altium-Bottom: 40
footprint CM3217
pins: 1 GND (power), 2 SDAT (io), 3 INT, 4 SET, 5 SCLK (in), 6 VDD (power)

## CODEC_ALC5623_0
designator U?, comment ALC5623
Altium-Right: 180; Altium-Bottom: 260
pins: 1 MICIP, 2 MICIN, 3 LINE_IN_L, 4 MIC2P, 5 MIC2N, 6 LINE_IN_R, 7 LRCK, 8 BCLK, 9 ADCDAT, 10 DACDAT, 11 MCLK, 12 DGND, 13 DCVDD, 14 DBVDD, 15 GPIO, 16 SCLK, 17 SDA, 18 CDEPOP, 19 AUXIN_L, 20 AUXIN_R, 21 AUXOUT_L, 22 AUXOUT_R, 23 LIN_OUT, 24 AGND2, 25 LIN_OUT_N, 26 AVDD2, 27 VREF, 28 AGND, 29 HP_OUT_R, 30 HP_OUT_L, 31 AVDD, 32 MICBAS, 33 GNDPAD

## Common Filter_0
designator L?
Altium-Right: 60; Altium-Bottom: 40
pins: 1, 2, 3, 4

## CON16B_0
designator J?
Altium-Right: 30; Altium-Bottom: 90
pins: 1, 2, 3, 4, 5, 6, 7, 8, 9, 10, 11, 12, 13, 14, 15, 16

## CON20A_0
designator J?
Altium-Right: 30; Altium-Bottom: 110
pins: 1, 2, 3, 4, 5, 6, 7, 8, 9, 10, 11, 12, 13, 14, 15, 16, 17, 18, 19, 20, 21, 22

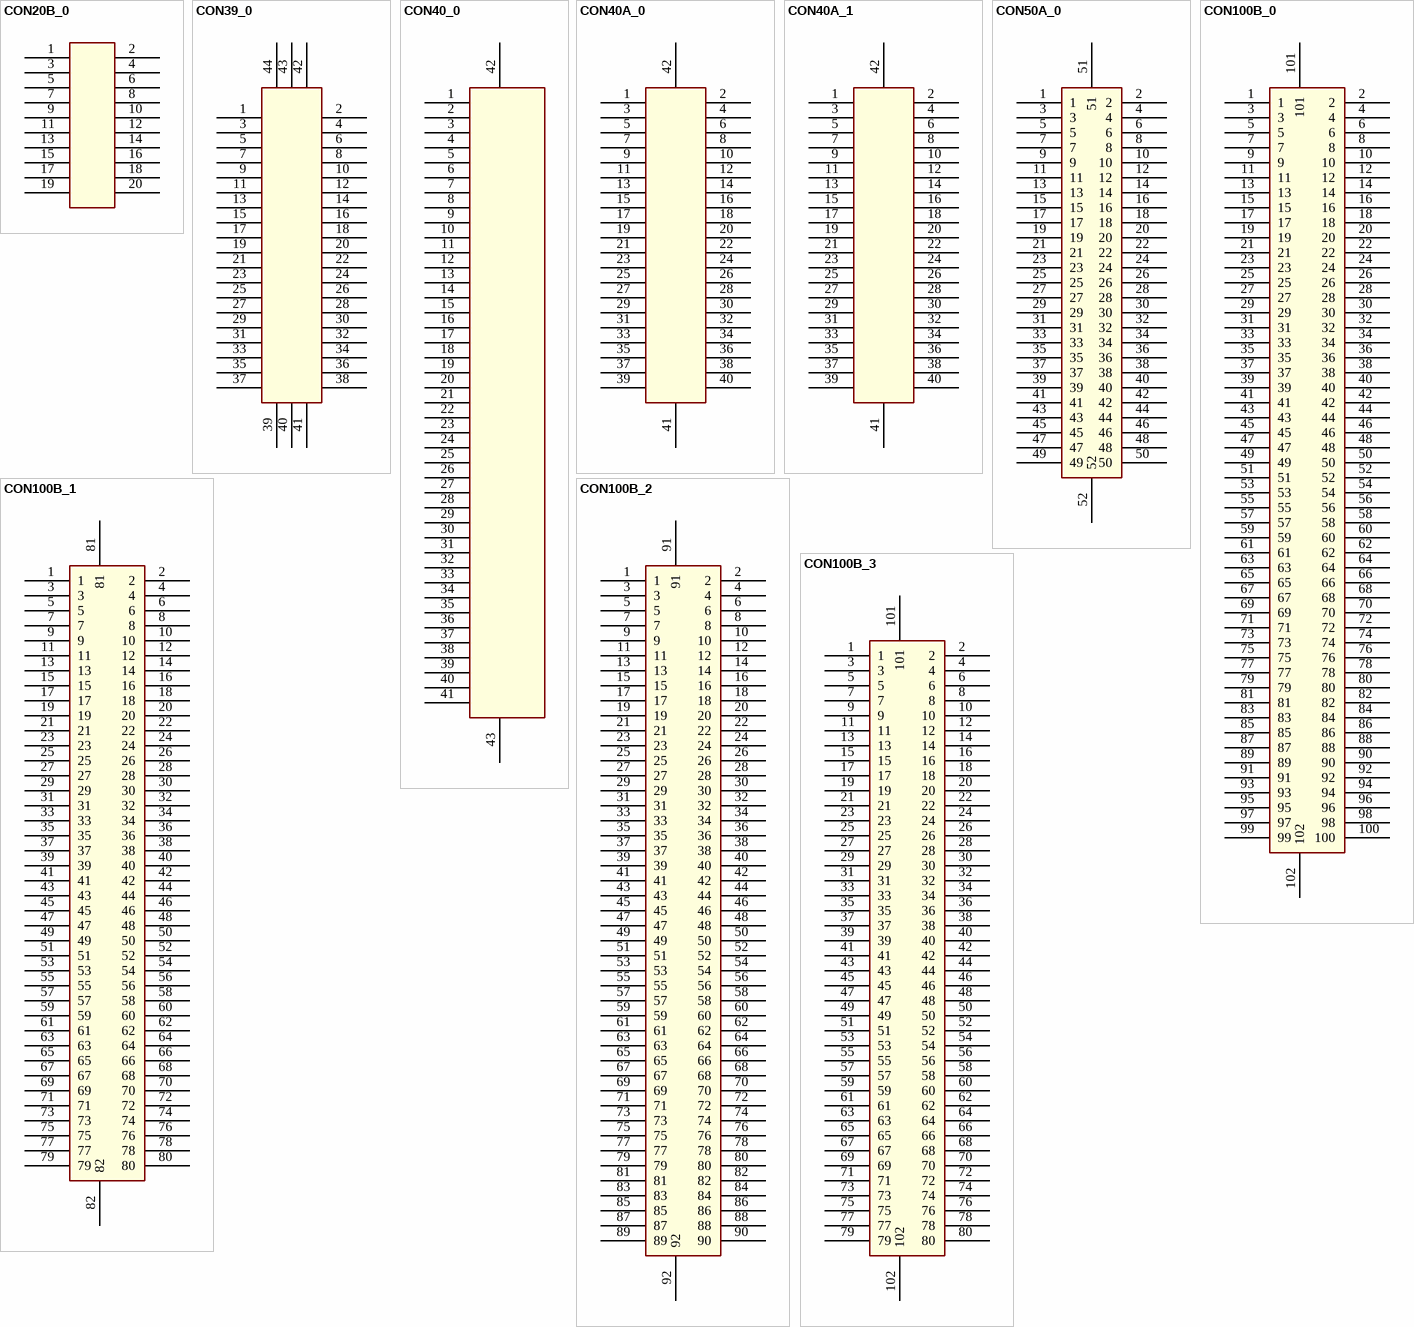
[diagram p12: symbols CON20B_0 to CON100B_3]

## CON20B_0
designator J?
Altium-Right: 30; Altium-Bottom: 110
pins: 1, 2, 3, 4, 5, 6, 7, 8, 9, 10, 11, 12, 13, 14, 15, 16, 17, 18, 19, 20

## CON39_0
designator J?
Altium-Right: 40; Altium-Bottom: 210
pins: 1, 2, 3, 4, 5, 6, 7, 8, 9, 10, 11, 12, 13, 14, 15, 16, 17, 18, 19, 20, 21, 22, 23, 24, 25, 26, 27, 28, 29, 30, 31, 32, 33, 34, 35, 36, 37, 38, 39, 40, 41, 42, 43, 44

## CON40_0
designator J?
Altium-Right: 50; Altium-Bottom: 420
pins: 1, 2, 3, 4, 5, 6, 7, 8, 9, 10, 11, 12, 13, 14, 15, 16, 17, 18, 19, 20, 21, 22, 23, 24, 25, 26, 27, 28, 29, 30, 31, 32, 33, 34, 35, 36, 37, 38, 39, 40, 41, 42, 43

## CON40A_0
designator J?
Altium-Right: 40; Altium-Bottom: 210
pins: 1, 2, 3, 4, 5, 6, 7, 8, 9, 10, 11, 12, 13, 14, 15, 16, 17, 18, 19, 20, 21, 22, 23, 24, 25, 26, 27, 28, 29, 30, 31, 32, 33, 34, 35, 36, 37, 38, 39, 40, 41, 42

## CON40A_1
designator J?
Altium-Right: 40; Altium-Bottom: 210
pins: 1, 2, 3, 4, 5, 6, 7, 8, 9, 10, 11, 12, 13, 14, 15, 16, 17, 18, 19, 20, 21, 22, 23, 24, 25, 26, 27, 28, 29, 30, 31, 32, 33, 34, 35, 36, 37, 38, 39, 40, 41, 42

## CON50A_0
designator J?
Altium-Right: 40; Altium-Bottom: 260
footprint 25PIN-S2.54
pins: 1, 2, 3, 4, 5, 6, 7, 8, 9, 10, 11, 12, 13, 14, 15, 16, 17, 18, 19, 20, 21, 22, 23, 24, 25, 26, 27, 28, 29, 30, 31, 32, 33, 34, 35, 36, 37, 38, 39, 40, 41, 42, 43, 44, 45, 46, 47, 48, 49, 50, 51, 52

## CON100B_0
designator J?
Altium-Right: 50; Altium-Bottom: 510
footprint 50PIN-S1.27
pins: 1, 2, 3, 4, 5, 6, 7, 8, 9, 10, 11, 12, 13, 14, 15, 16, 17, 18, 19, 20, 21, 22, 23, 24, 25, 26, 27, 28, 29, 30, 31, 32, 33, 34, 35, 36, 37, 38, 39, 40, 41, 42, 43, 44, 45, 46, 47, 48, 49, 50, 51, 52, 53, 54, 55, 56, 57, 58, 59, 60, 61, 62, 63, 64, 65, 66, 67, 68, 69, 70, 71, 72, 73, 74, 75, 76, 77, 78, 79, 80, 81, 82, 83, 84, 85, 86, 87, 88, 89, 90, 91, 92, 93, 94, 95, 96, 97, 98, 99, 100, 101, 102

## CON100B_1
designator J?
Altium-Right: 50; Altium-Bottom: 410
footprint 50PIN-S1.27
pins: 1, 2, 3, 4, 5, 6, 7, 8, 9, 10, 11, 12, 13, 14, 15, 16, 17, 18, 19, 20, 21, 22, 23, 24, 25, 26, 27, 28, 29, 30, 31, 32, 33, 34, 35, 36, 37, 38, 39, 40, 41, 42, 43, 44, 45, 46, 47, 48, 49, 50, 51, 52, 53, 54, 55, 56, 57, 58, 59, 60, 61, 62, 63, 64, 65, 66, 67, 68, 69, 70, 71, 72, 73, 74, 75, 76, 77, 78, 79, 80, 81, 82

## CON100B_2
designator J?
Altium-Right: 50; Altium-Bottom: 460
footprint 50PIN-S1.27
pins: 1, 2, 3, 4, 5, 6, 7, 8, 9, 10, 11, 12, 13, 14, 15, 16, 17, 18, 19, 20, 21, 22, 23, 24, 25, 26, 27, 28, 29, 30, 31, 32, 33, 34, 35, 36, 37, 38, 39, 40, 41, 42, 43, 44, 45, 46, 47, 48, 49, 50, 51, 52, 53, 54, 55, 56, 57, 58, 59, 60, 61, 62, 63, 64, 65, 66, 67, 68, 69, 70, 71, 72, 73, 74, 75, 76, 77, 78, 79, 80, 81, 82, 83, 84, 85, 86, 87, 88, 89, 90, 91, 92

## CON100B_3
designator J?
Altium-Right: 50; Altium-Bottom: 410
footprint 50PIN-S1.27
pins: 1, 2, 3, 4, 5, 6, 7, 8, 9, 10, 11, 12, 13, 14, 15, 16, 17, 18, 19, 20, 21, 22, 23, 24, 25, 26, 27, 28, 29, 30, 31, 32, 33, 34, 35, 36, 37, 38, 39, 40, 41, 42, 43, 44, 45, 46, 47, 48, 49, 50, 51, 52, 53, 54, 55, 56, 57, 58, 59, 60, 61, 62, 63, 64, 65, 66, 67, 68, 69, 70, 71, 72, 73, 74, 75, 76, 77, 78, 79, 80, 101, 102

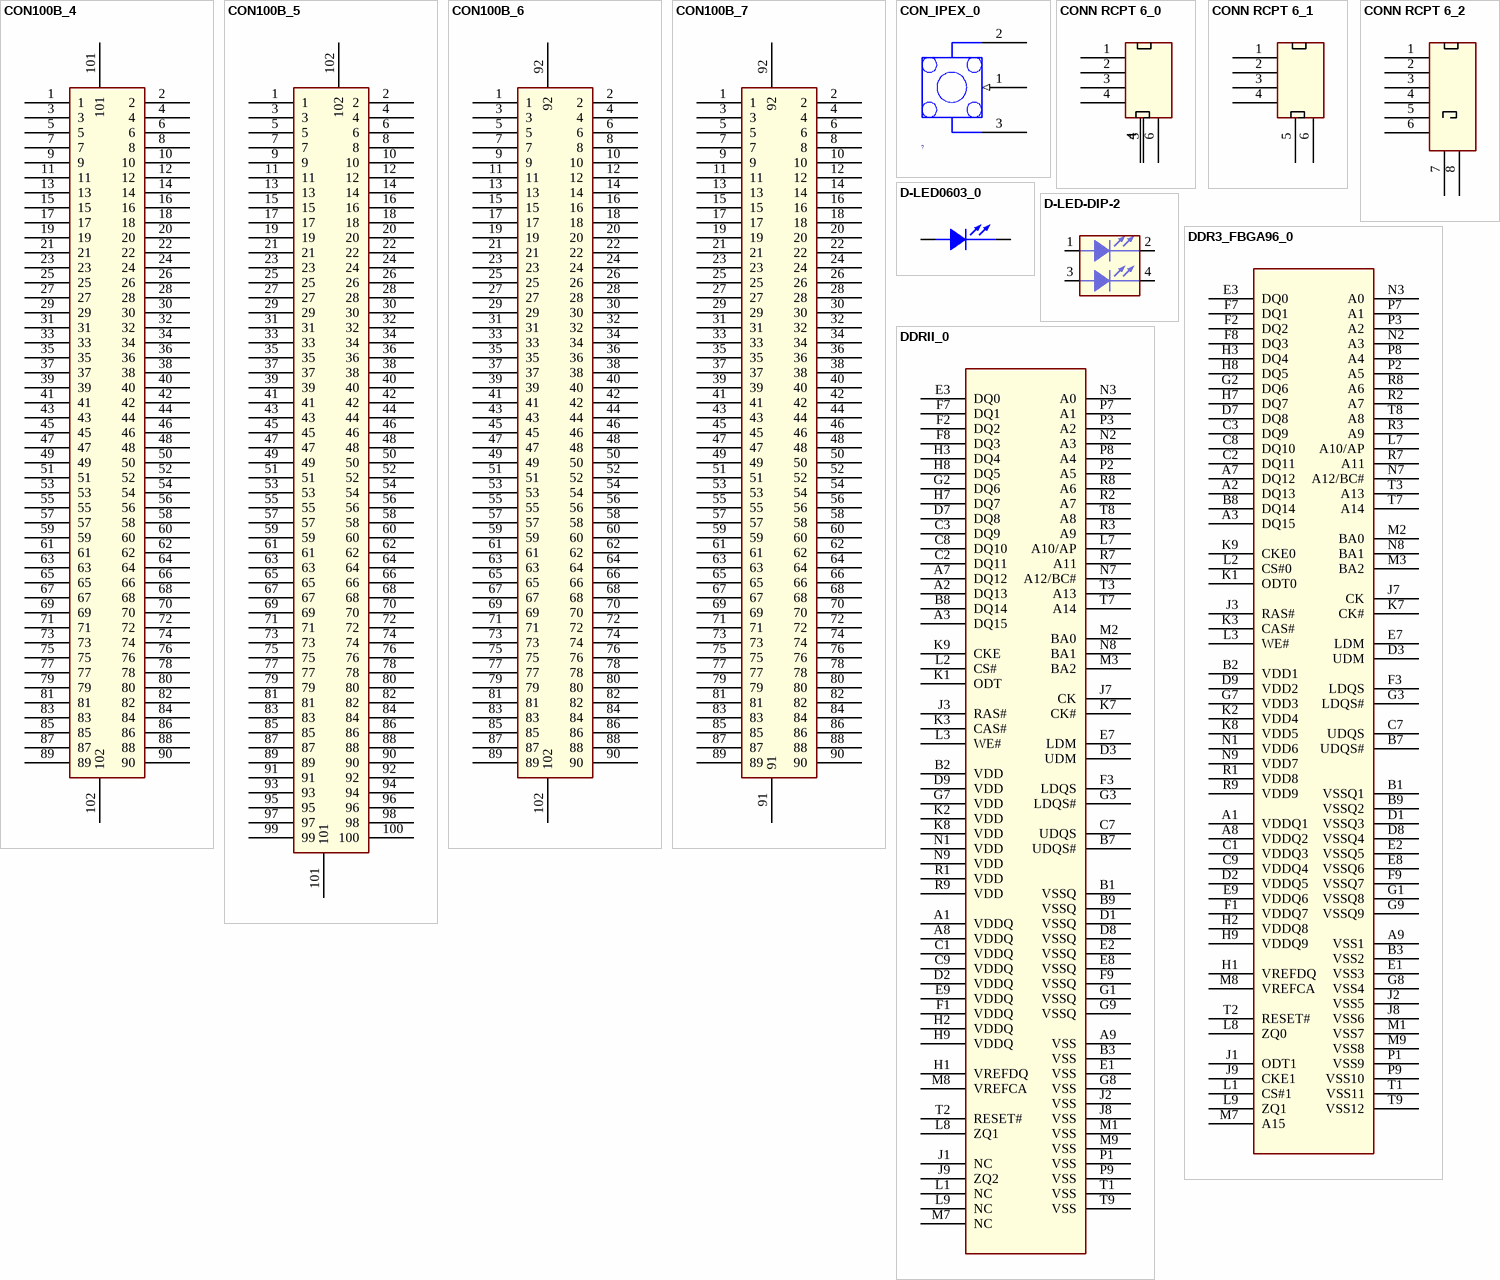
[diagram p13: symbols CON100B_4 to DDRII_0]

## CON100B_4
designator J?
Altium-Right: 50; Altium-Bottom: 460
footprint 50PIN-S1.27
pins: 1, 2, 3, 4, 5, 6, 7, 8, 9, 10, 11, 12, 13, 14, 15, 16, 17, 18, 19, 20, 21, 22, 23, 24, 25, 26, 27, 28, 29, 30, 31, 32, 33, 34, 35, 36, 37, 38, 39, 40, 41, 42, 43, 44, 45, 46, 47, 48, 49, 50, 51, 52, 53, 54, 55, 56, 57, 58, 59, 60, 61, 62, 63, 64, 65, 66, 67, 68, 69, 70, 71, 72, 73, 74, 75, 76, 77, 78, 79, 80, 81, 82, 83, 84, 85, 86, 87, 88, 89, 90, 101, 102

## CON100B_5
designator J?
Altium-Right: 50; Altium-Bottom: 510
footprint 50PIN-S1.27
pins: 1, 2, 3, 4, 5, 6, 7, 8, 9, 10, 11, 12, 13, 14, 15, 16, 17, 18, 19, 20, 21, 22, 23, 24, 25, 26, 27, 28, 29, 30, 31, 32, 33, 34, 35, 36, 37, 38, 39, 40, 41, 42, 43, 44, 45, 46, 47, 48, 49, 50, 51, 52, 53, 54, 55, 56, 57, 58, 59, 60, 61, 62, 63, 64, 65, 66, 67, 68, 69, 70, 71, 72, 73, 74, 75, 76, 77, 78, 79, 80, 81, 82, 83, 84, 85, 86, 87, 88, 89, 90, 91, 92, 93, 94, 95, 96, 97, 98, 99, 100, 101, 102

## CON100B_6
designator J?
Altium-Right: 50; Altium-Bottom: 460
footprint 50PIN-S1.27
pins: 1, 2, 3, 4, 5, 6, 7, 8, 9, 10, 11, 12, 13, 14, 15, 16, 17, 18, 19, 20, 21, 22, 23, 24, 25, 26, 27, 28, 29, 30, 31, 32, 33, 34, 35, 36, 37, 38, 39, 40, 41, 42, 43, 44, 45, 46, 47, 48, 49, 50, 51, 52, 53, 54, 55, 56, 57, 58, 59, 60, 61, 62, 63, 64, 65, 66, 67, 68, 69, 70, 71, 72, 73, 74, 75, 76, 77, 78, 79, 80, 81, 82, 83, 84, 85, 86, 87, 88, 89, 90, 92, 102

## CON100B_7
designator J?
Altium-Right: 50; Altium-Bottom: 460
footprint 50PIN-S1.27
pins: 1, 2, 3, 4, 5, 6, 7, 8, 9, 10, 11, 12, 13, 14, 15, 16, 17, 18, 19, 20, 21, 22, 23, 24, 25, 26, 27, 28, 29, 30, 31, 32, 33, 34, 35, 36, 37, 38, 39, 40, 41, 42, 43, 44, 45, 46, 47, 48, 49, 50, 51, 52, 53, 54, 55, 56, 57, 58, 59, 60, 61, 62, 63, 64, 65, 66, 67, 68, 69, 70, 71, 72, 73, 74, 75, 76, 77, 78, 79, 80, 81, 82, 83, 84, 85, 86, 87, 88, 89, 90, 91, 92

## CON_IPEX_0
designator ?, comment CON_IPEX  (value not drawn)
?; OriginalSymbolOrigin: (-100,200); Altium-Right: 40; Altium-Bottom: 80
pins: 1 IN (in), 2 GND1 (power), 3 GND2 (power)

## CONN RCPT 6_0
designator J?
Altium-Right: 31; Altium-Bottom: 50
pins: 1, 2, 3, 4, 4, 4, 4, 5, 6

## CONN RCPT 6_1
designator J?
Altium-Right: 31; Altium-Bottom: 50
pins: 1, 2, 3, 4, 5, 6

## CONN RCPT 6_2
designator J?
Altium-Right: 31; Altium-Bottom: 72
pins: 1, 2, 3, 4, 5, 6, 7, 8

## D-LED0603_0
designator LED?
Altium-Right: 40; Altium-Bottom: 20
pins: 1 ANODE, 2 CATHODE

## D-LED-DIP-2
designator LED?
Altium-Right: 40
pins: 1, 2, 3, 4

## DDR3_FBGA96_0
designator U?
Altium-Right: 80; Altium-Bottom: 590
footprint DDRII_X16
pins: A1 VDDQ1, A2 DQ13, A3 DQ15, A7 DQ12, A8 VDDQ2, A9 VSS1, B1 VSSQ1, B2 VDD1, B3 VSS2, B7 UDQS#, B8 DQ14, B9 VSSQ2, C1 VDDQ3, C2 DQ11, C3 DQ9, C7 UDQS, C8 DQ10, C9 VDDQ4, D1 VSSQ3, D2 VDDQ5, D3 UDM, D7 DQ8, D8 VSSQ4, D9 VDD2, E1 VSS3, E2 VSSQ5, E3 DQ0, E7 LDM, E8 VSSQ6, E9 VDDQ6, F1 VDDQ7, F2 DQ2, F3 LDQS, F7 DQ1, F8 DQ3, F9 VSSQ7, G1 VSSQ8, G2 DQ6, G3 LDQS#, G7 VDD3, G8 VSS4, G9 VSSQ9, H1 VREFDQ, H2 VDDQ8, H3 DQ4, H7 DQ7, H8 DQ5, H9 VDDQ9, J1 ODT1, J2 VSS5, J3 RAS#, J7 CK, J8 VSS6, J9 CKE1, K1 ODT0, K2 VDD4, K3 CAS#, K7 CK#, K8 VDD5, K9 CKE0, L1 CS#1, L2 CS#0, L3 WE#, L7 A10/AP, L8 ZQ0, L9 ZQ1, M1 VSS7, M2 BA0, M3 BA2, M7 A15, M8 VREFCA, M9 VSS8, N1 VDD6, N2 A3, N3 A0, N7 A12/BC#, N8 BA1, N9 VDD7, P1 VSS9, P2 A5, P3 A2, P7 A1, P8 A4, P9 VSS10, R1 VDD8, R2 A7, R3 A9, R7 A11, R8 A6, R9 VDD9, T1 VSS11, T2 RESET#, T3 A13, T7 A14, T8 A8, T9 VSS12

## DDRII_0
designator U?
Altium-Right: 80; Altium-Bottom: 590
footprint DDRII_X16
pins: A1 VDDQ, A2 DQ13, A3 DQ15, A7 DQ12, A8 VDDQ, A9 VSS, B1 VSSQ, B2 VDD, B3 VSS, B7 UDQS#, B8 DQ14, B9 VSSQ, C1 VDDQ, C2 DQ11, C3 DQ9, C7 UDQS, C8 DQ10, C9 VDDQ, D1 VSSQ, D2 VDDQ, D3 UDM, D7 DQ8, D8 VSSQ, D9 VDD, E1 VSS, E2 VSSQ, E3 DQ0, E7 LDM, E8 VSSQ, E9 VDDQ, F1 VDDQ, F2 DQ2, F3 LDQS, F7 DQ1, F8 DQ3, F9 VSSQ, G1 VSSQ, G2 DQ6, G3 LDQS#, G7 VDD, G8 VSS, G9 VSSQ, H1 VREFDQ, H2 VDDQ, H3 DQ4, H7 DQ7, H8 DQ5, H9 VDDQ, J1 NC, J2 VSS, J3 RAS#, J7 CK, J8 VSS, J9 ZQ2, K1 ODT, K2 VDD, K3 CAS#, K7 CK#, K8 VDD, K9 CKE, L1 NC, L2 CS#, L3 WE#, L7 A10/AP, L8 ZQ1, L9 NC, M1 VSS, M2 BA0, M3 BA2, M7 NC, M8 VREFCA, M9 VSS, N1 VDD, N2 A3, N3 A0, N7 A12/BC#, N8 BA1, N9 VDD, P1 VSS, P2 A5, P3 A2, P7 A1, P8 A4, P9 VSS, R1 VDD, R2 A7, R3 A9, R7 A11, R8 A6, R9 VDD, T1 VSS, T2 RESET#, T3 A13, T7 A14, T8 A8, T9 VSS

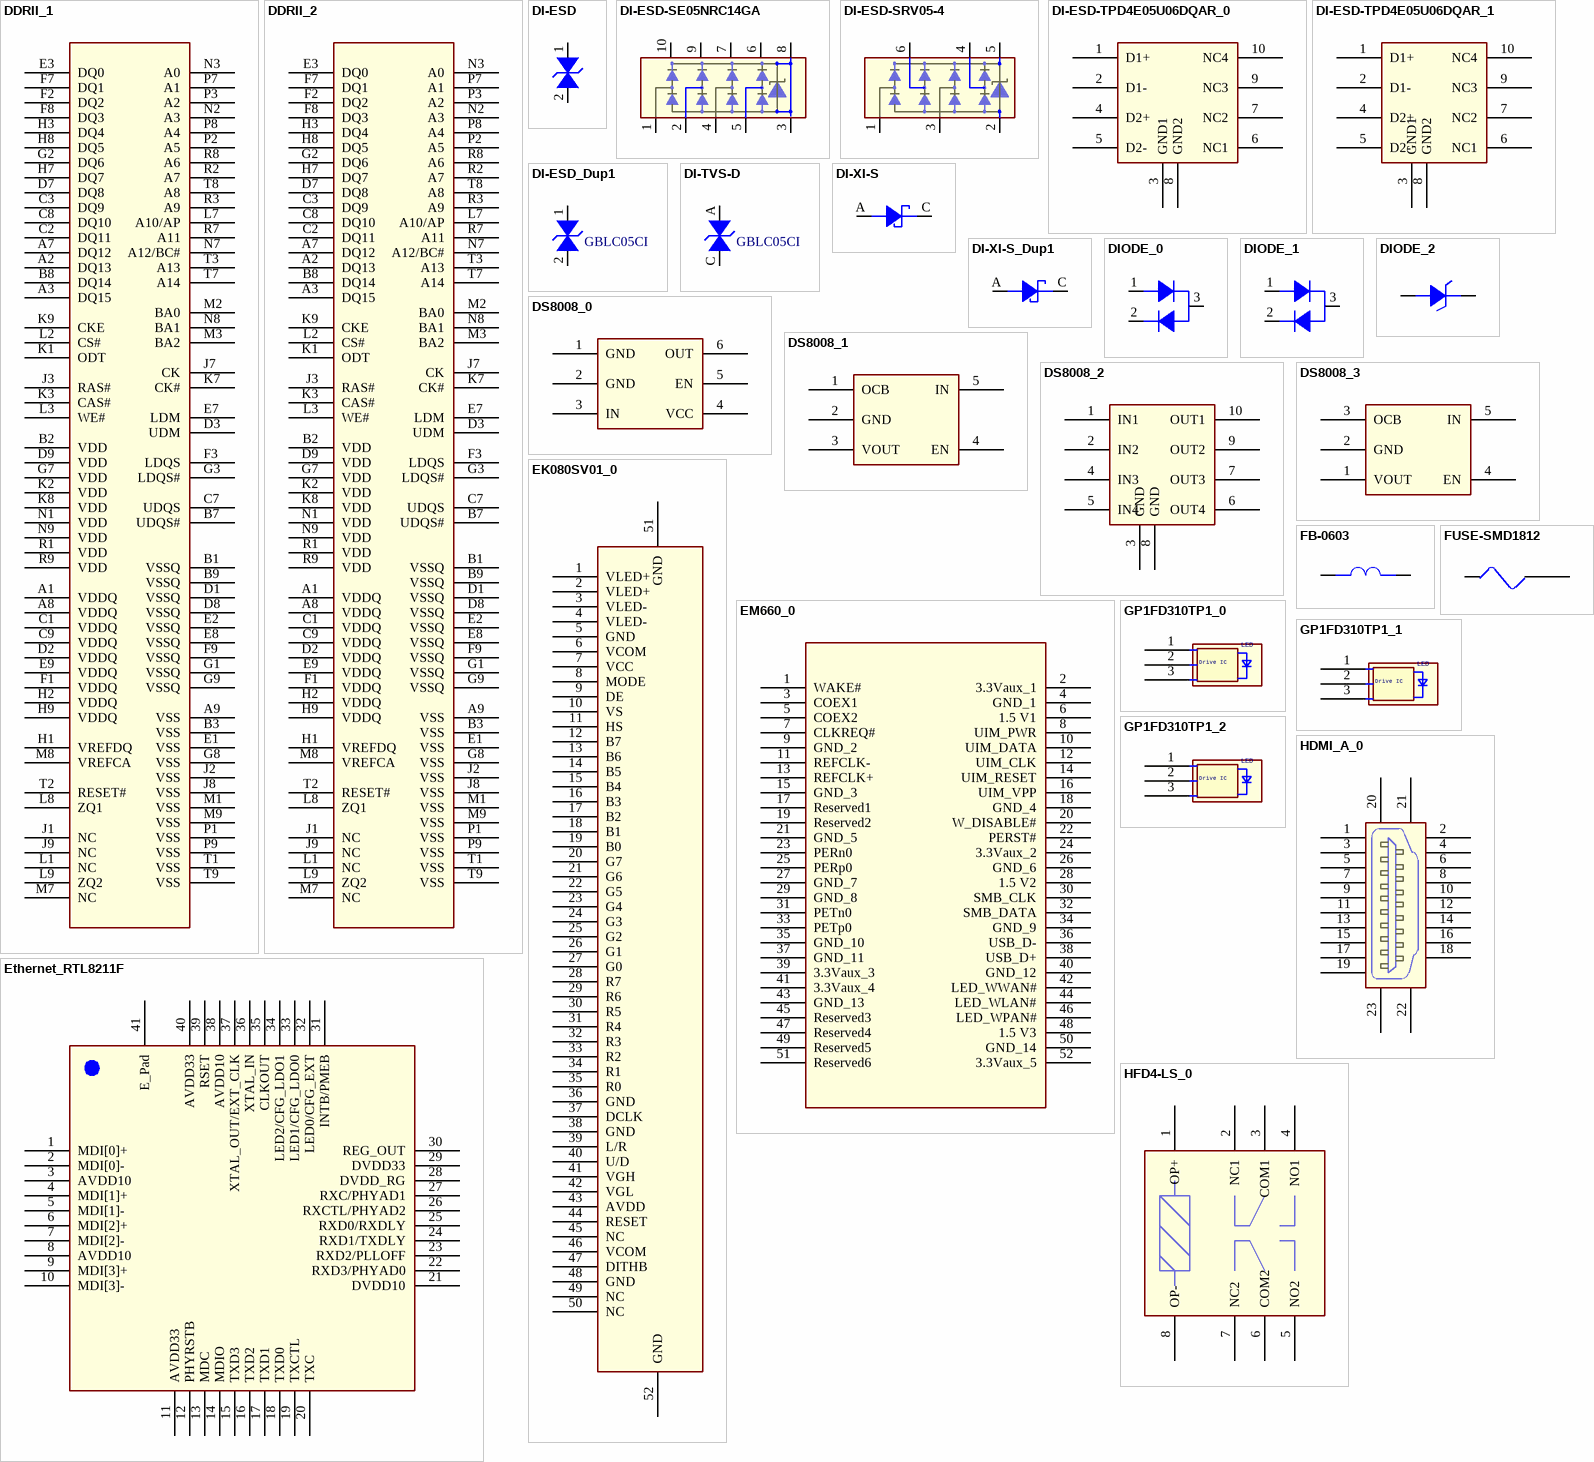
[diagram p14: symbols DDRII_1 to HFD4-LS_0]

## DDRII_1
designator U?
Altium-Right: 80; Altium-Bottom: 590
footprint DDRII_X16
pins: A1 VDDQ, A2 DQ13, A3 DQ15, A7 DQ12, A8 VDDQ, A9 VSS, B1 VSSQ, B2 VDD, B3 VSS, B7 UDQS#, B8 DQ14, B9 VSSQ, C1 VDDQ, C2 DQ11, C3 DQ9, C7 UDQS, C8 DQ10, C9 VDDQ, D1 VSSQ, D2 VDDQ, D3 UDM, D7 DQ8, D8 VSSQ, D9 VDD, E1 VSS, E2 VSSQ, E3 DQ0, E7 LDM, E8 VSSQ, E9 VDDQ, F1 VDDQ, F2 DQ2, F3 LDQS, F7 DQ1, F8 DQ3, F9 VSSQ, G1 VSSQ, G2 DQ6, G3 LDQS#, G7 VDD, G8 VSS, G9 VSSQ, H1 VREFDQ, H2 VDDQ, H3 DQ4, H7 DQ7, H8 DQ5, H9 VDDQ, J1 NC, J2 VSS, J3 RAS#, J7 CK, J8 VSS, J9 NC, K1 ODT, K2 VDD, K3 CAS#, K7 CK#, K8 VDD, K9 CKE, L1 NC, L2 CS#, L3 WE#, L7 A10/AP, L8 ZQ1, L9 ZQ2, M1 VSS, M2 BA0, M3 BA2, M7 NC, M8 VREFCA, M9 VSS, N1 VDD, N2 A3, N3 A0, N7 A12/BC#, N8 BA1, N9 VDD, P1 VSS, P2 A5, P3 A2, P7 A1, P8 A4, P9 VSS, R1 VDD, R2 A7, R3 A9, R7 A11, R8 A6, R9 VDD, T1 VSS, T2 RESET#, T3 A13, T7 A14, T8 A8, T9 VSS

## DDRII_2
designator U?
Altium-Right: 80; Altium-Bottom: 590
footprint DDRII_X16
pins: A1 VDDQ, A2 DQ13, A3 DQ15, A7 DQ12, A8 VDDQ, A9 VSS, B1 VSSQ, B2 VDD, B3 VSS, B7 UDQS#, B8 DQ14, B9 VSSQ, C1 VDDQ, C2 DQ11, C3 DQ9, C7 UDQS, C8 DQ10, C9 VDDQ, D1 VSSQ, D2 VDDQ, D3 UDM, D7 DQ8, D8 VSSQ, D9 VDD, E1 VSS, E2 VSSQ, E3 DQ0, E7 LDM, E8 VSSQ, E9 VDDQ, F1 VDDQ, F2 DQ2, F3 LDQS, F7 DQ1, F8 DQ3, F9 VSSQ, G1 VSSQ, G2 DQ6, G3 LDQS#, G7 VDD, G8 VSS, G9 VSSQ, H1 VREFDQ, H2 VDDQ, H3 DQ4, H7 DQ7, H8 DQ5, H9 VDDQ, J1 NC, J2 VSS, J3 RAS#, J7 CK, J8 VSS, J9 NC, K1 ODT, K2 VDD, K3 CAS#, K7 CK#, K8 VDD, K9 CKE, L1 NC, L2 CS#, L3 WE#, L7 A10/AP, L8 ZQ1, L9 ZQ2, M1 VSS, M2 BA0, M3 BA2, M7 NC, M8 VREFCA, M9 VSS, N1 VDD, N2 A3, N3 A0, N7 A12/BC#, N8 BA1, N9 VDD, P1 VSS, P2 A5, P3 A2, P7 A1, P8 A4, P9 VSS, R1 VDD, R2 A7, R3 A9, R7 A11, R8 A6, R9 VDD, T1 VSS, T2 RESET#, T3 A13, T7 A14, T8 A8, T9 VSS

## DI-ESD
designator T?
ESD 0402; Manufacturer: INPAQ; Manufacture P/N: MLVG04021R0UV18; Part Number: EB3.1R0UV18402A; PN Type: Varistor; Altium-Right: 20
pins: 1 I/O2, 2 I/O1

## DI-ESD-SE05NRC14GA
designator D?
Altium-Right: 110; Altium-Bottom: 40
pins: 1, 2, 3, 4, 5, 6, 7, 8, 9, 10

## DI-ESD-SRV05-4
designator D?
Altium-Right: 100; Altium-Bottom: 40
pins: 1, 2, 3, 4, 5, 6

## DI-ESD-TPD4E05U06DQAR_0
designator U?
Altium-Right: 80
pins: 1 D1+, 2 D1-, 3 GND1, 4 D2+, 5 D2-, 6 NC1, 7 NC2, 8 GND2, 9 NC3, 10 NC4

## DI-ESD-TPD4E05U06DQAR_1
designator U?
Altium-Right: 70; Altium-Bottom: 80
pins: 1 D1+, 2 D1-, 3 GND1, 4 D2+, 5 D2-, 6 NC1, 7 NC2, 8 GND2, 9 NC3, 10 NC4

## DI-ESD_Dup1
designator T?, comment GBLC05CI
ESD 0402; Manufacturer: INPAQ; Manufacture P/N: MLVG04021R0UV18; Part Number: EB3.1R0UV18402A; PN Type: Varistor; Altium-Right: 20
pins: 1 I/O2, 2 I/O1

## DI-TVS-D
designator T?, comment GBLC05CI
ESD 0402; Part Number: EB3.1R0UV18402A; Manufacture P/N: MLVG04021R0UV18; Manufacturer: INPAQ; PN Type: Varistor; Altium-Right: 20
pins: A I/O2, C I/O1

## DI-XI-S
designator D?
CLASS: IC; Altium-Right: 30; Altium-Bottom: 20
pins: A, C

## DI-XI-S_Dup1
designator D?
CLASS: IC; Altium-Right: 30; Altium-Bottom: 20
pins: A, C

## DIODE_0
designator D?
Altium-Right: 30; Altium-Bottom: 40
pins: 1 ANODE, 2 CATHODE, 3 COMMON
